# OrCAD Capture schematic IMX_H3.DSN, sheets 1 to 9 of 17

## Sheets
1 PAGE01: title: i.MX28 Home Health Hub; rev: 1.0; company: Freescale Semiconductor; note: SCH-XXXXX PDF: SPF-XXXXX; note: 6501 William Cannon Drive West; note: Austin, TX 78735-8598
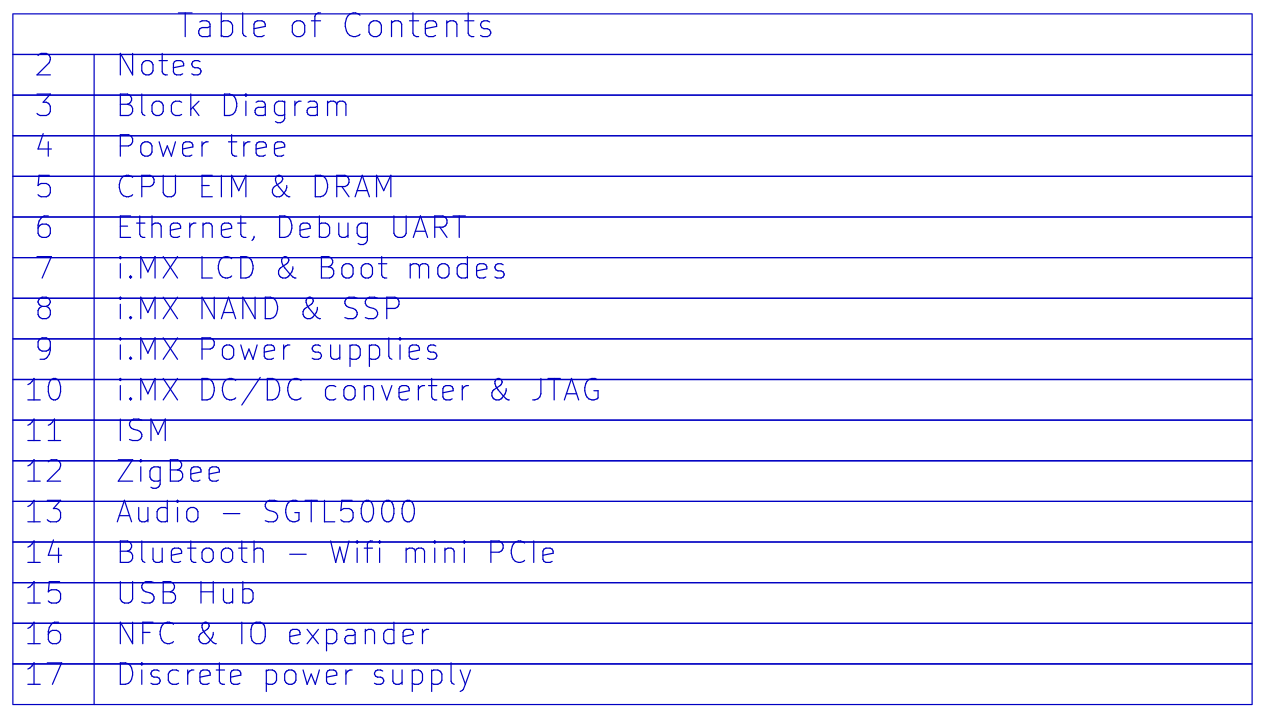
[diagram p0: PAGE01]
2 PAGE02 - Notes & revision table
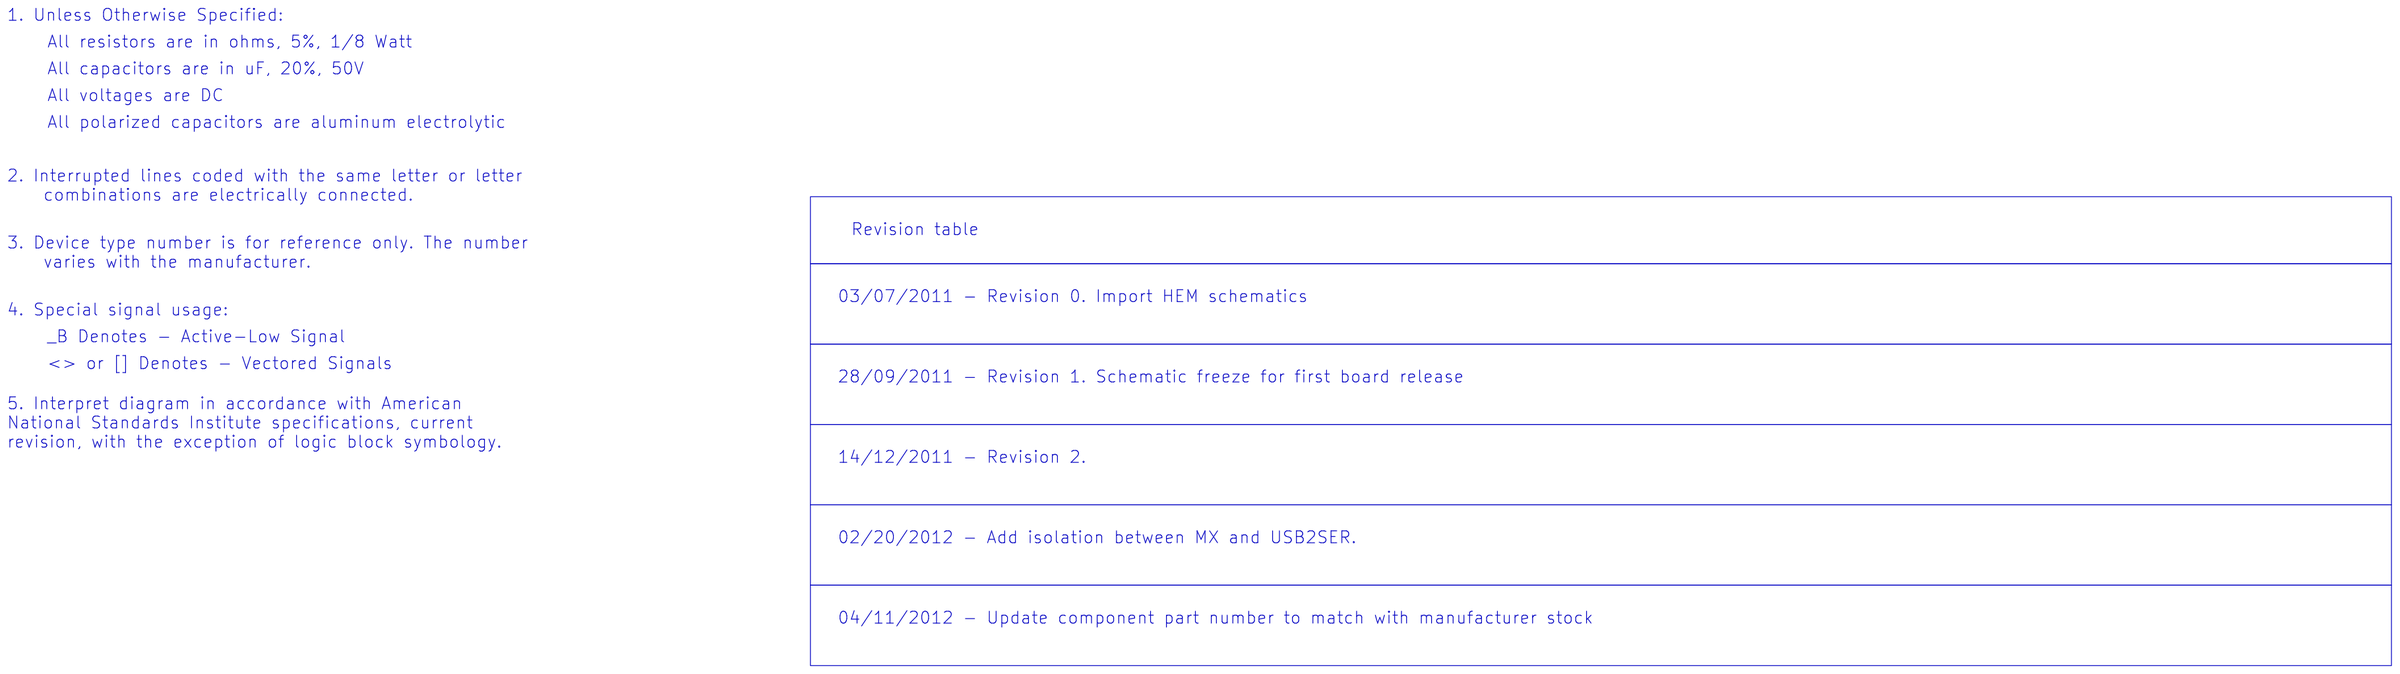
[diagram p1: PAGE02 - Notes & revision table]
3 PAGE03 - Block diagram
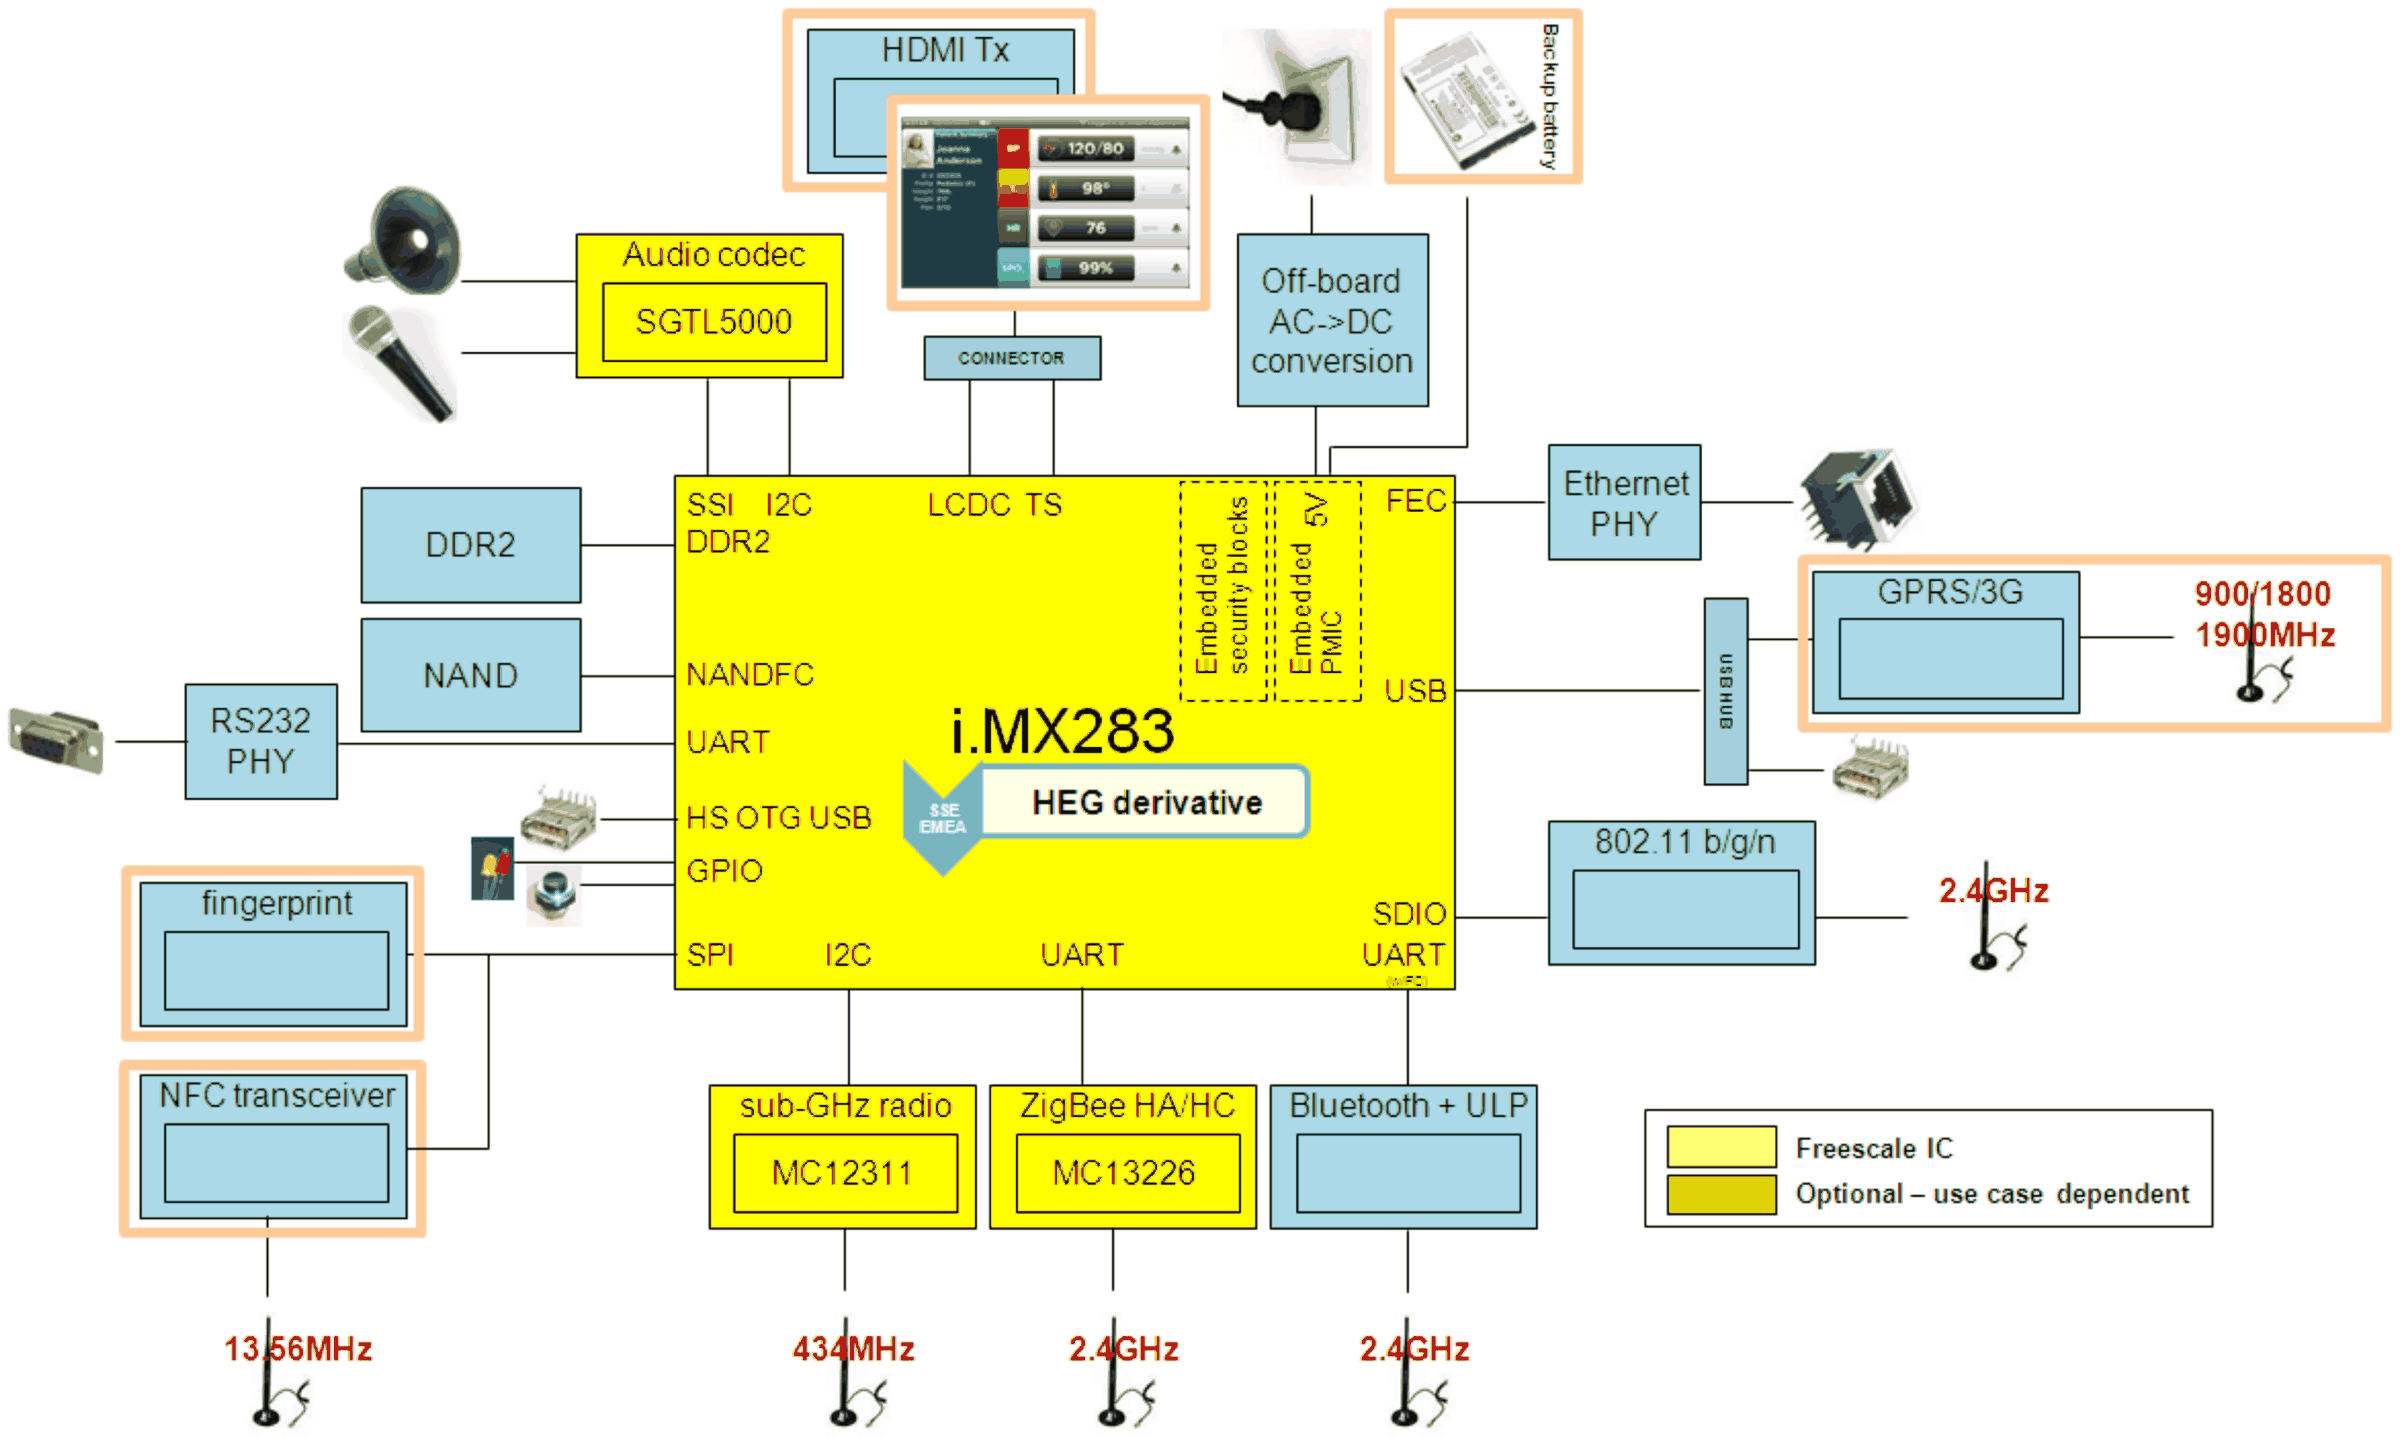
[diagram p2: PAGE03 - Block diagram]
4 PAGE04 - Power Tree
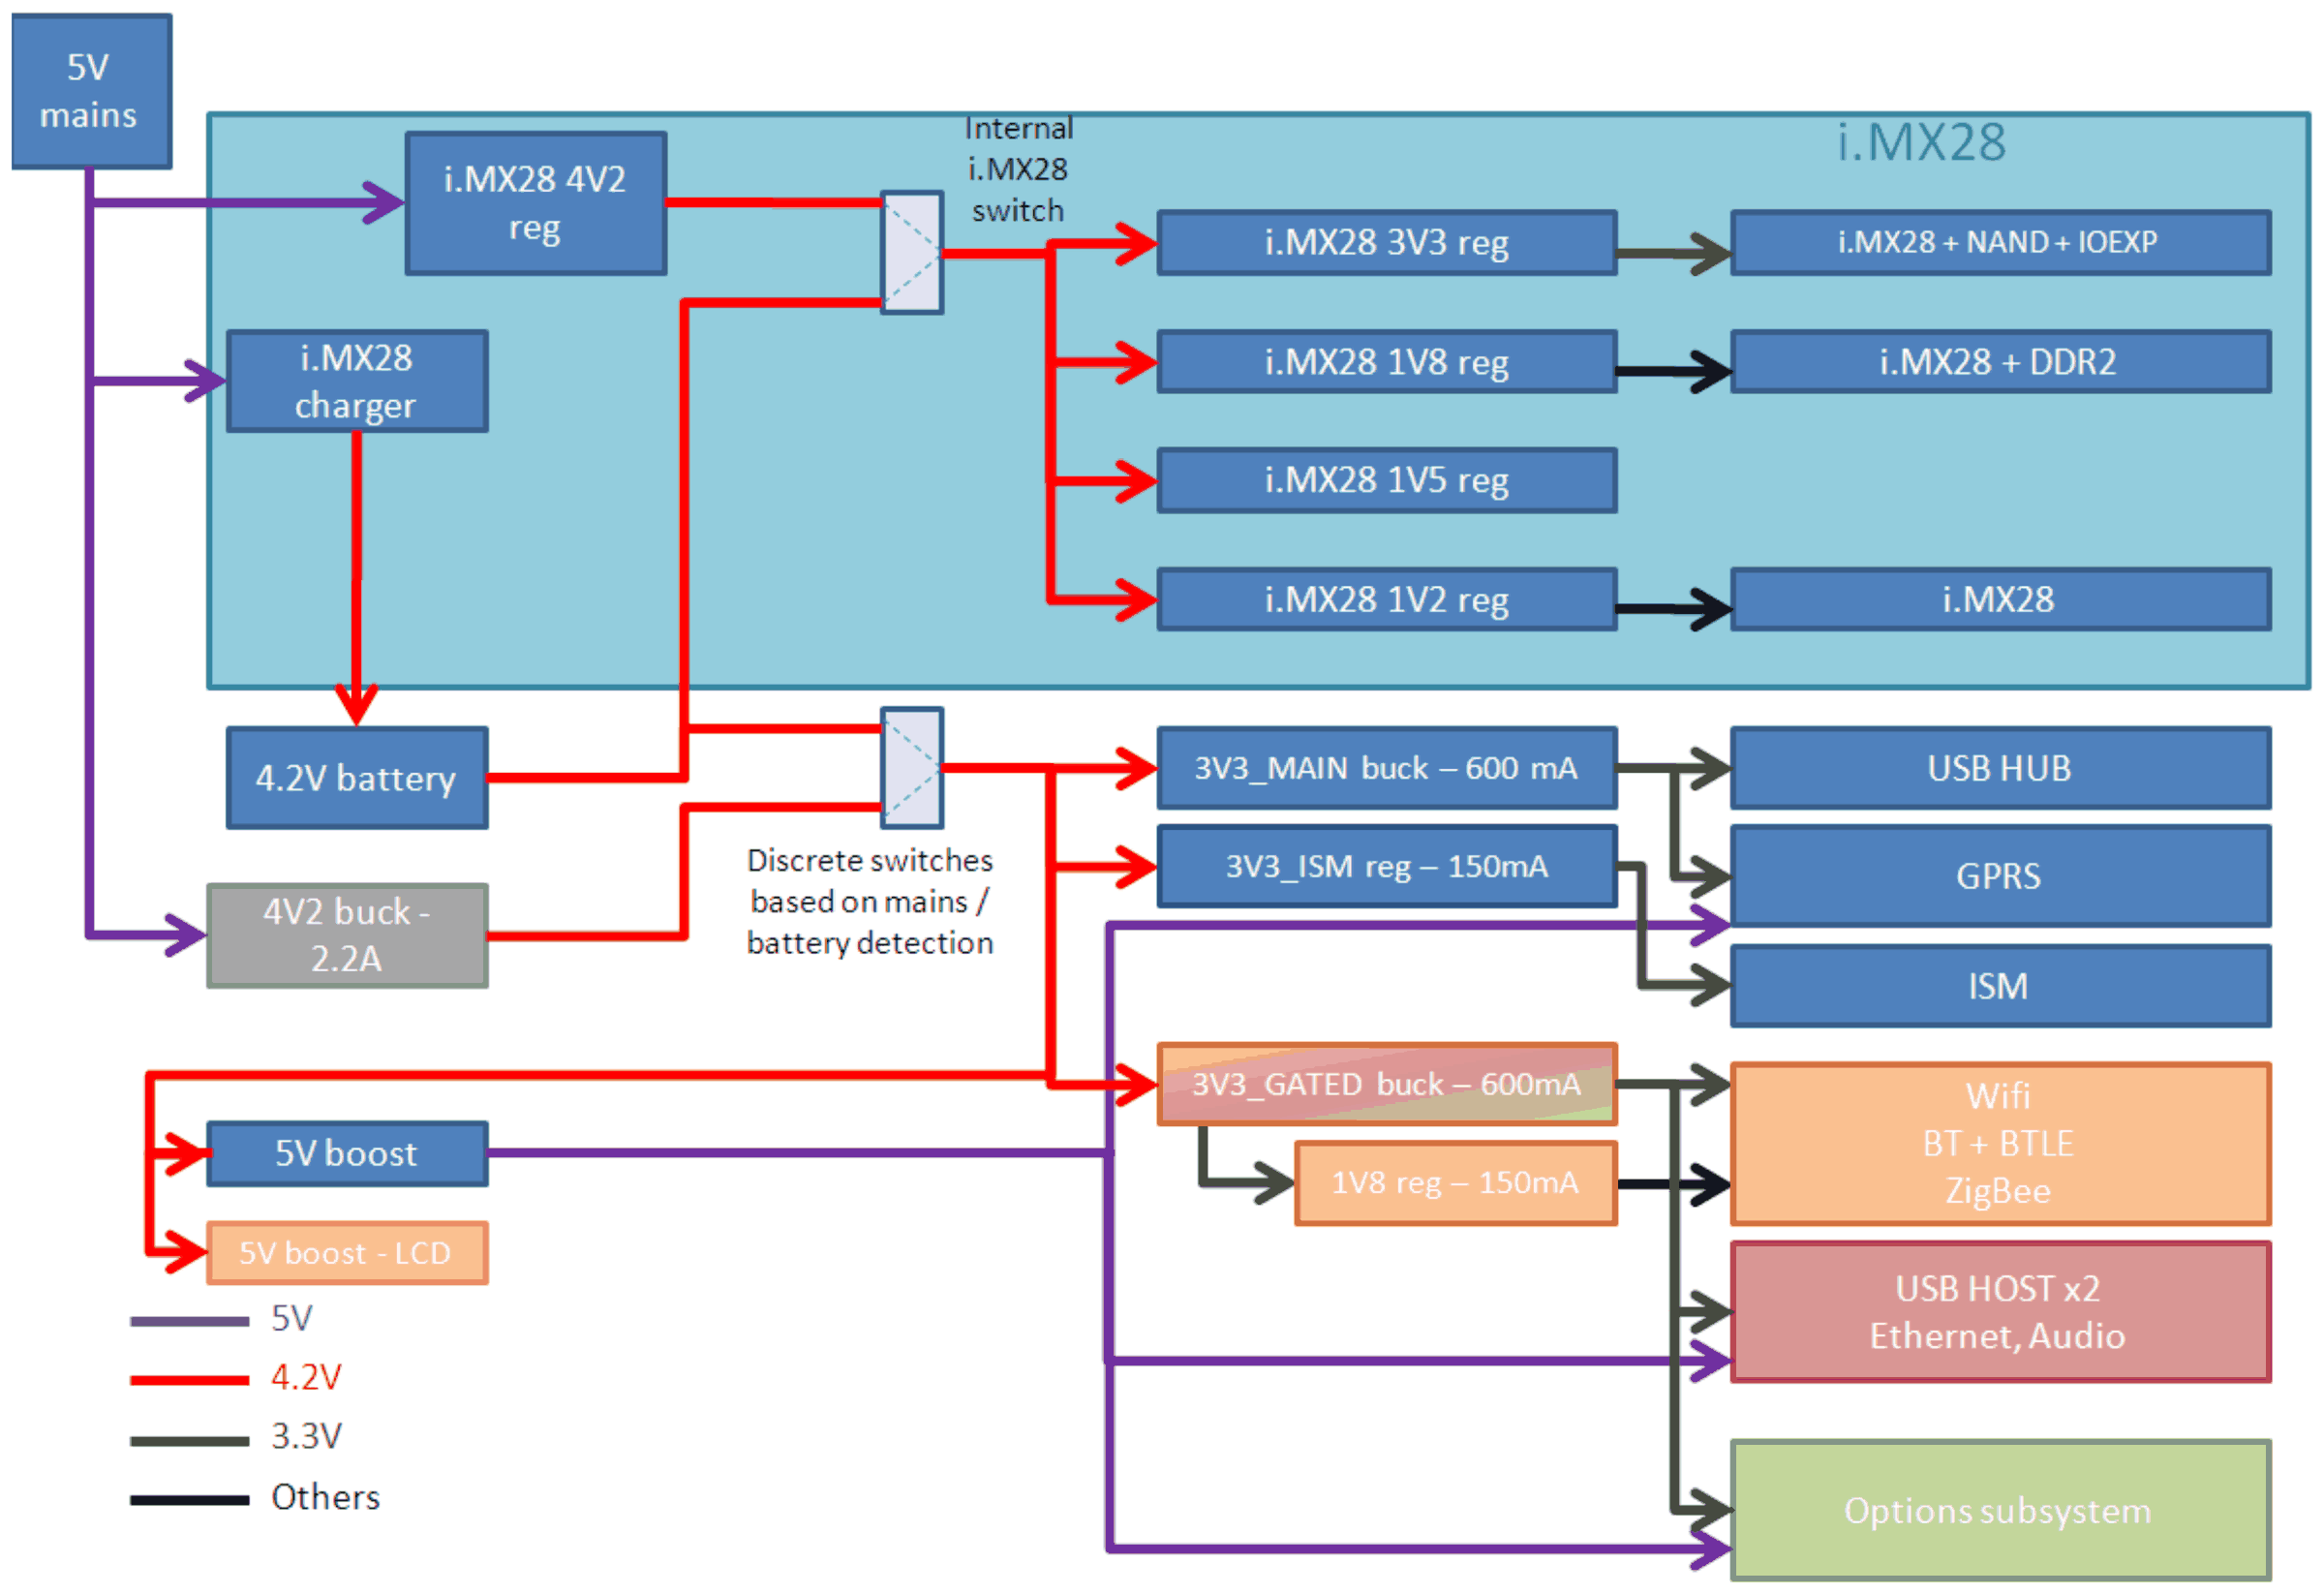
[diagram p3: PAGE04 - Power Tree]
5 PAGE05 - CPU EIM-DRAM: size C
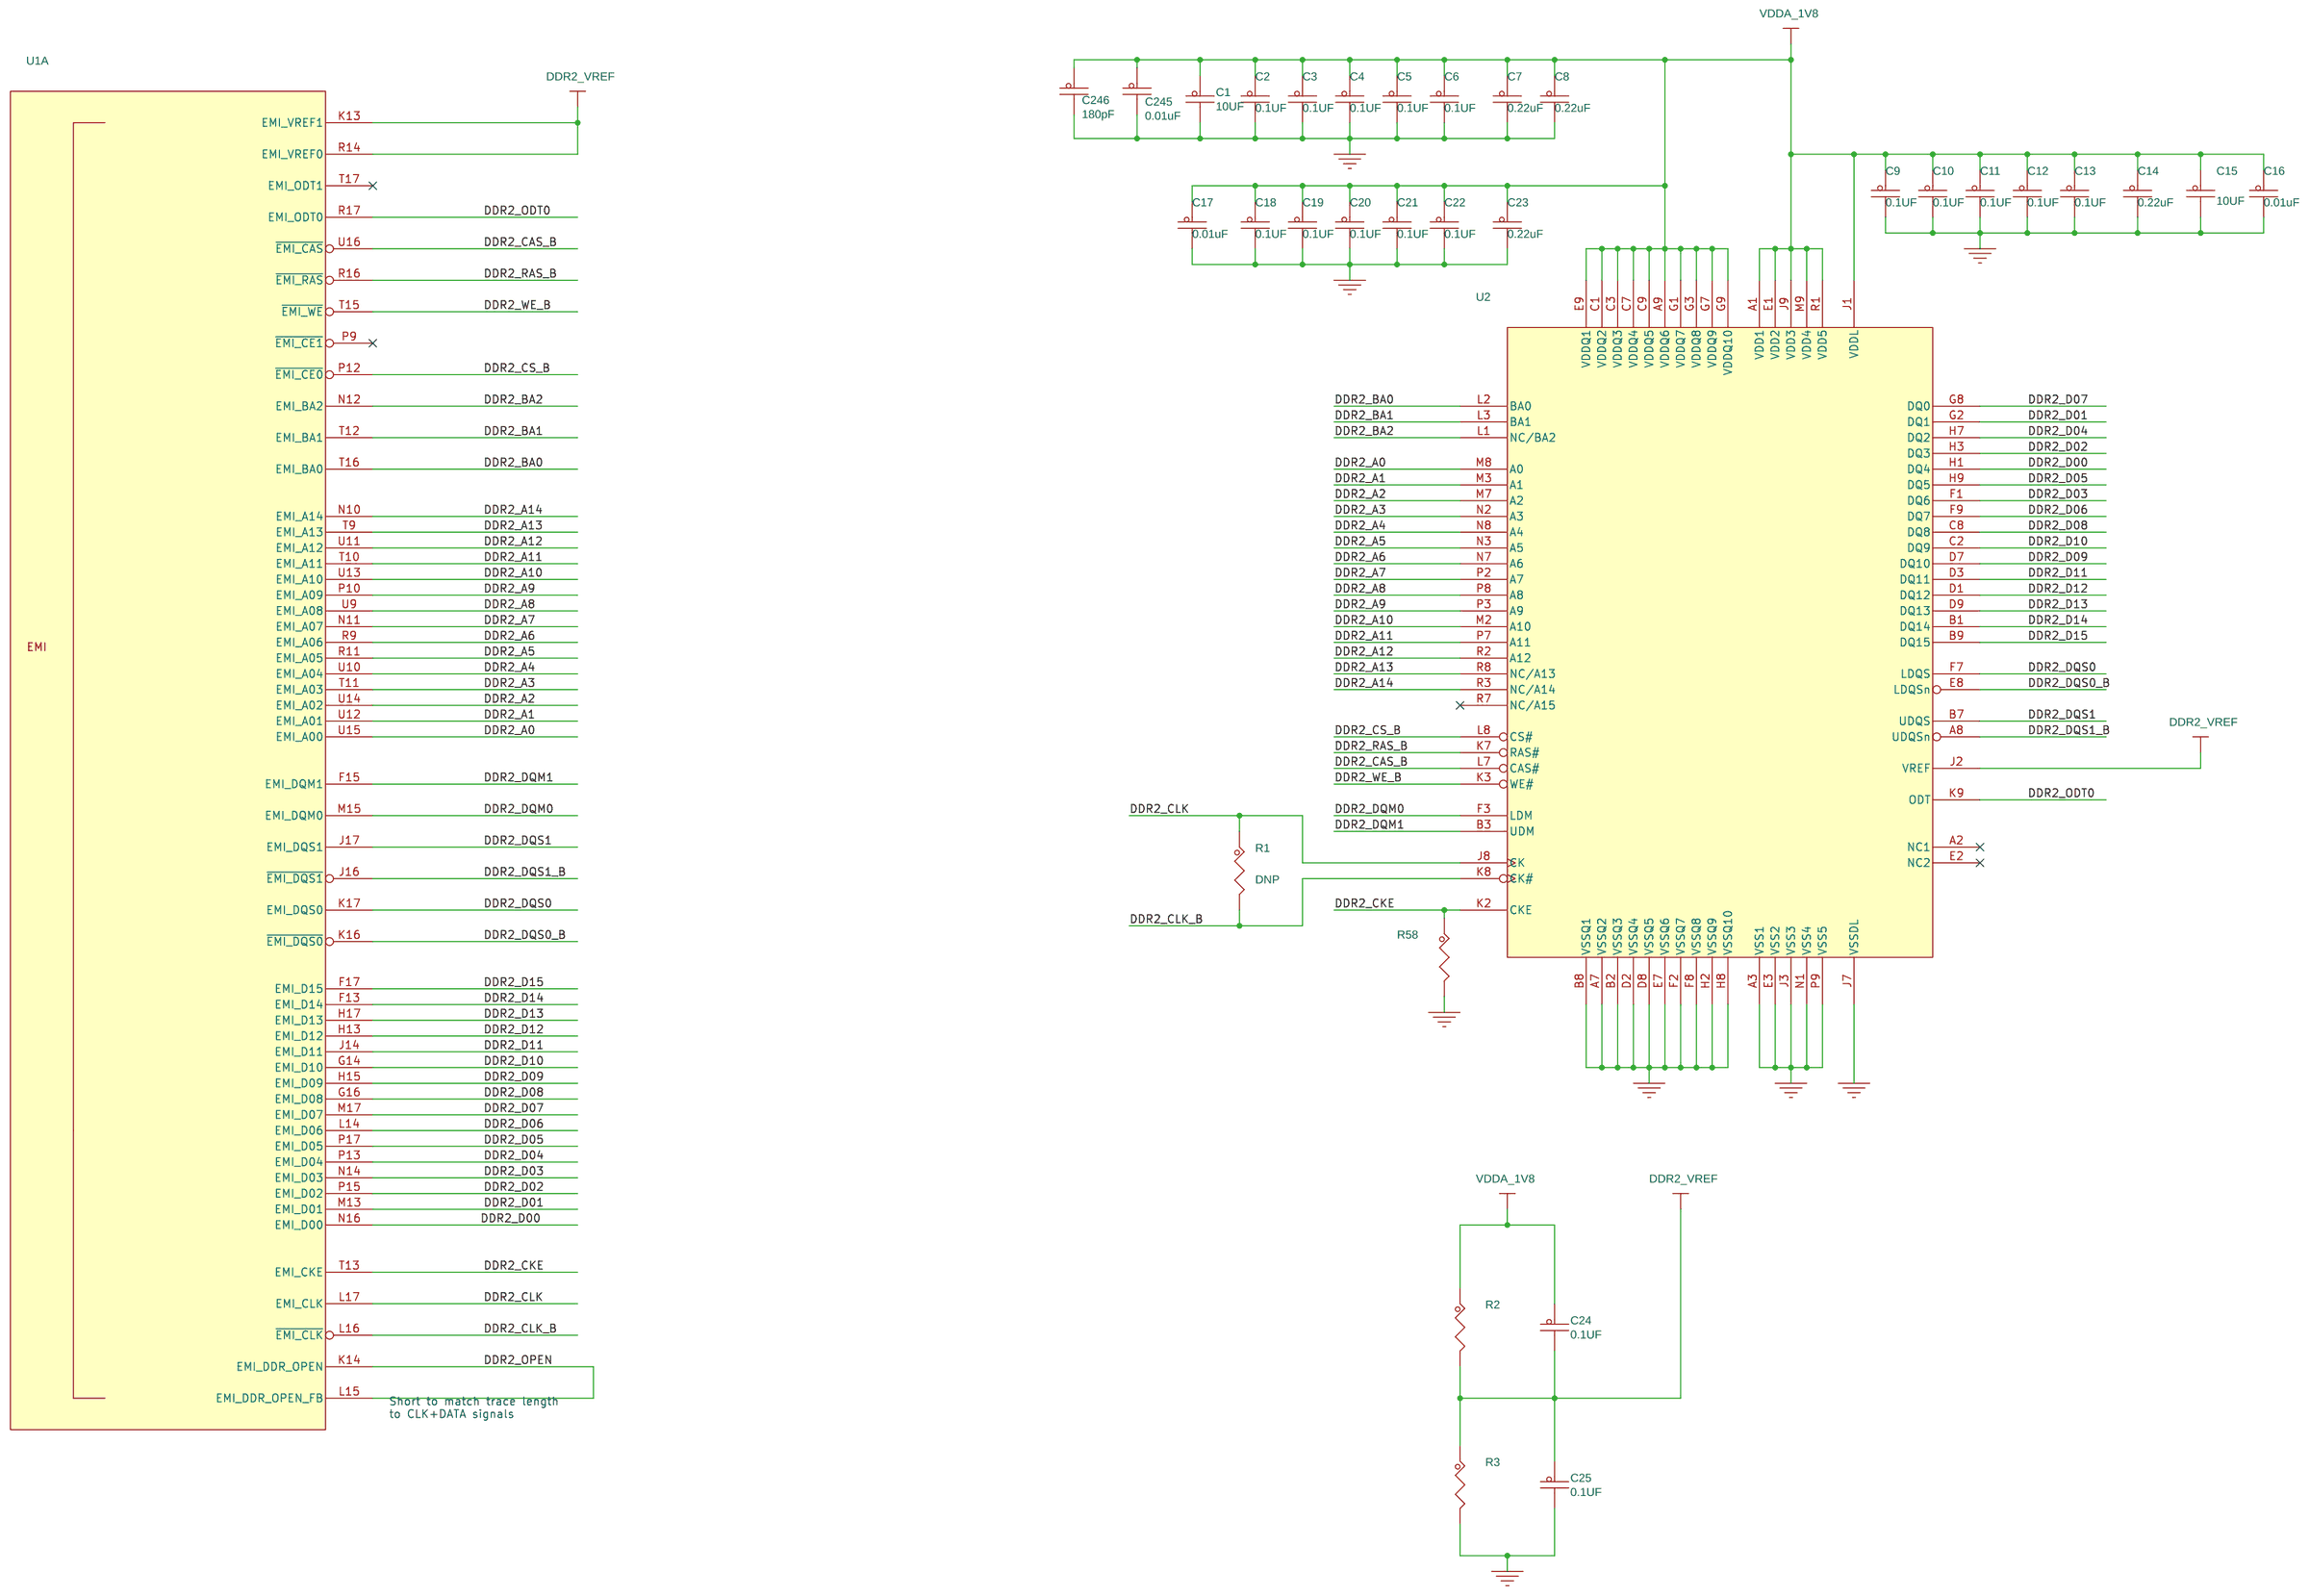
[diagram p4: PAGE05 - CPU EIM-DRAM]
6 PAGE06 - CPU ETH, UART: size C
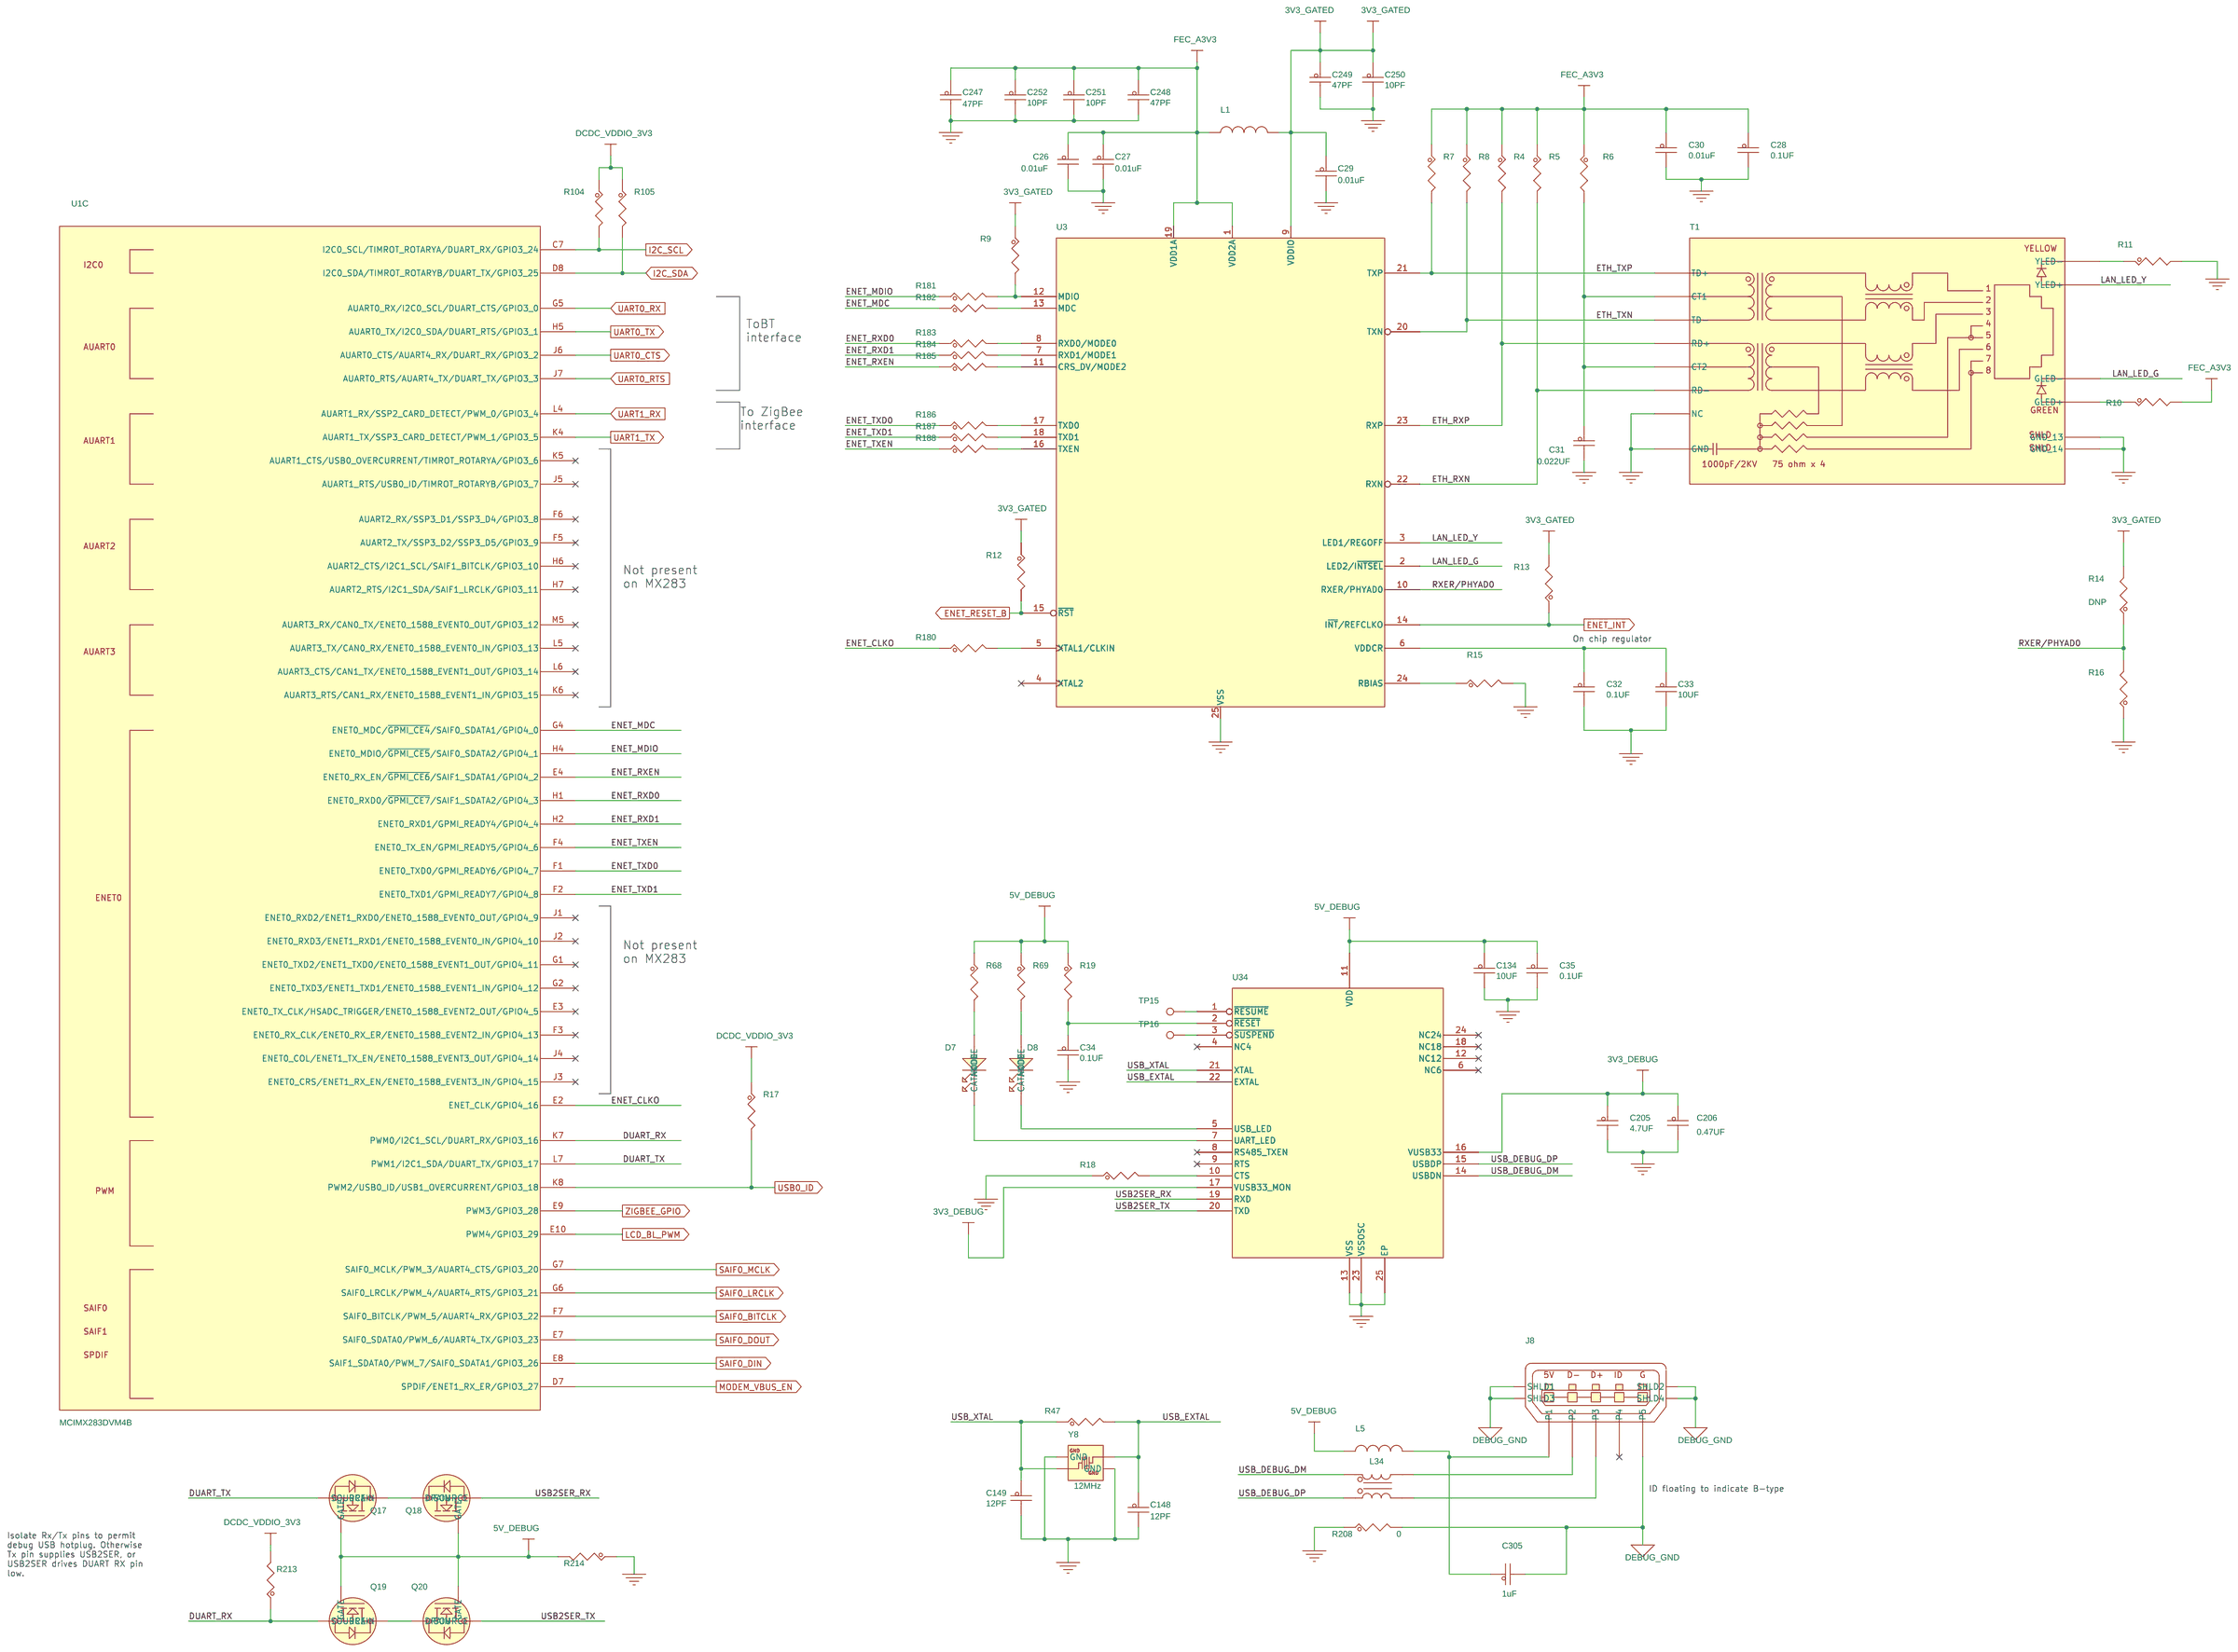
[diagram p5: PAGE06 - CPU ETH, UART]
7 PAGE07 - CPU LCD & LEDs: size C
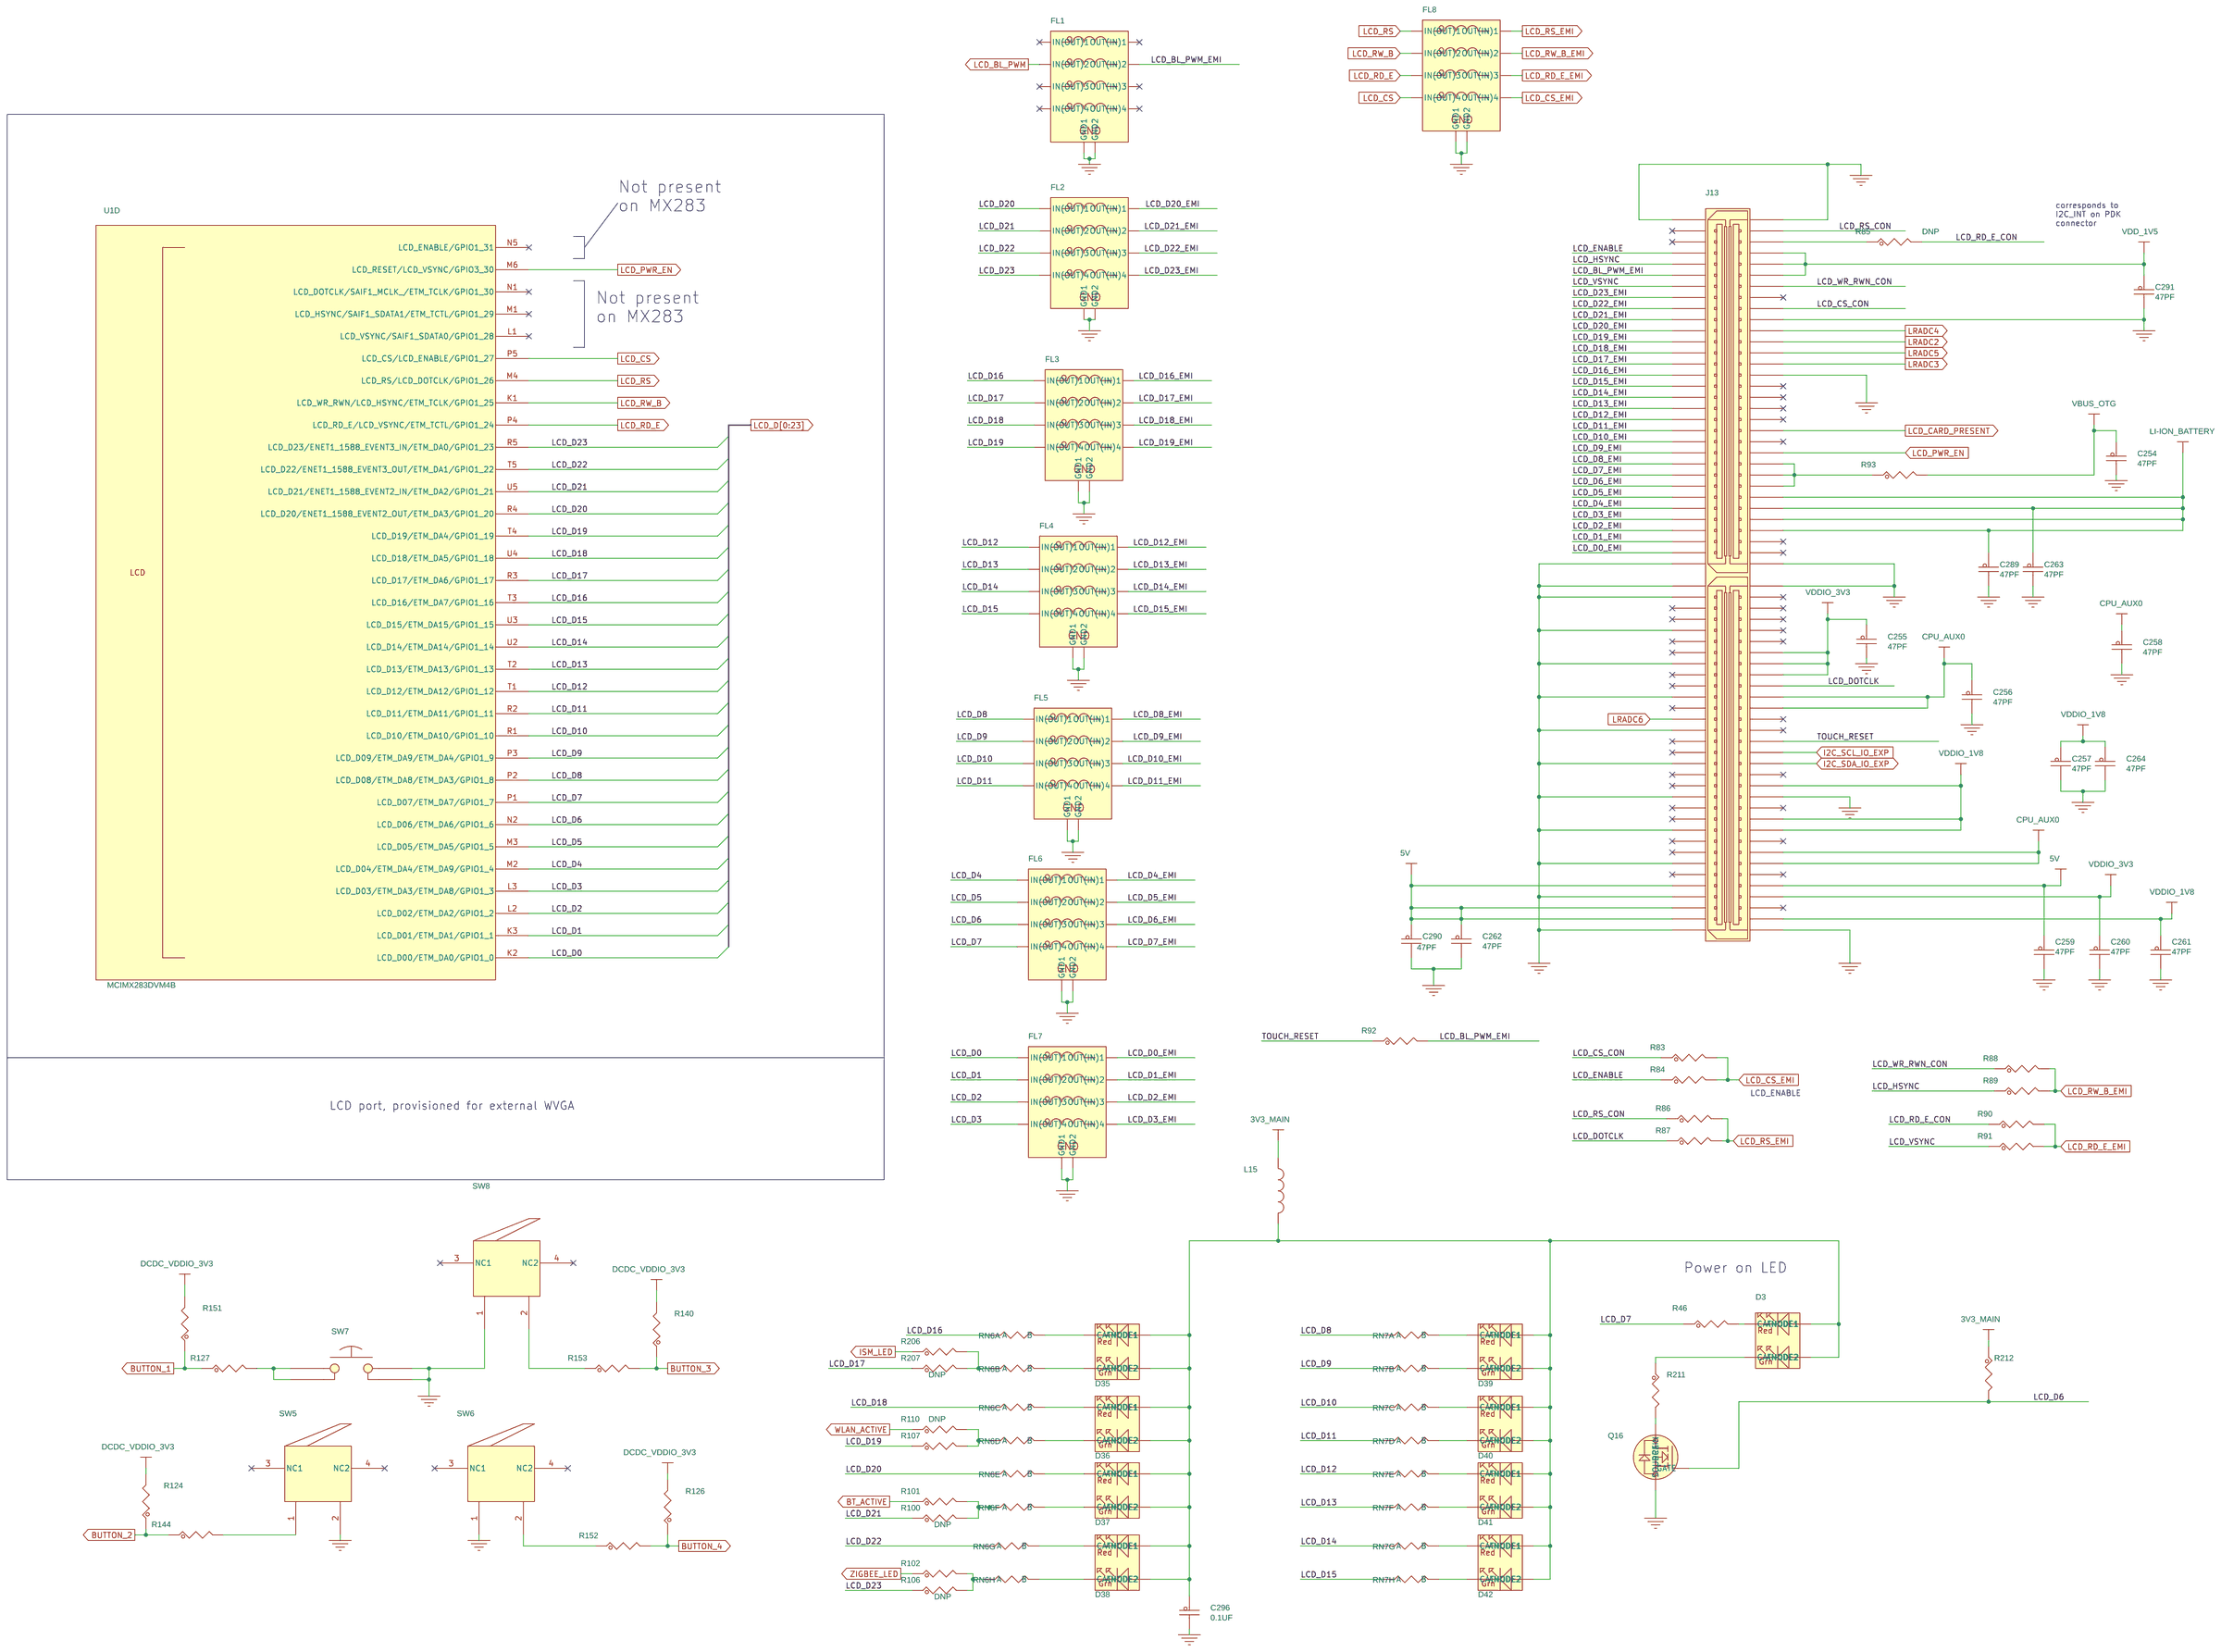
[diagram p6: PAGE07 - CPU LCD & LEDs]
8 PAGE08 - CPU NAND, SSPs: size C
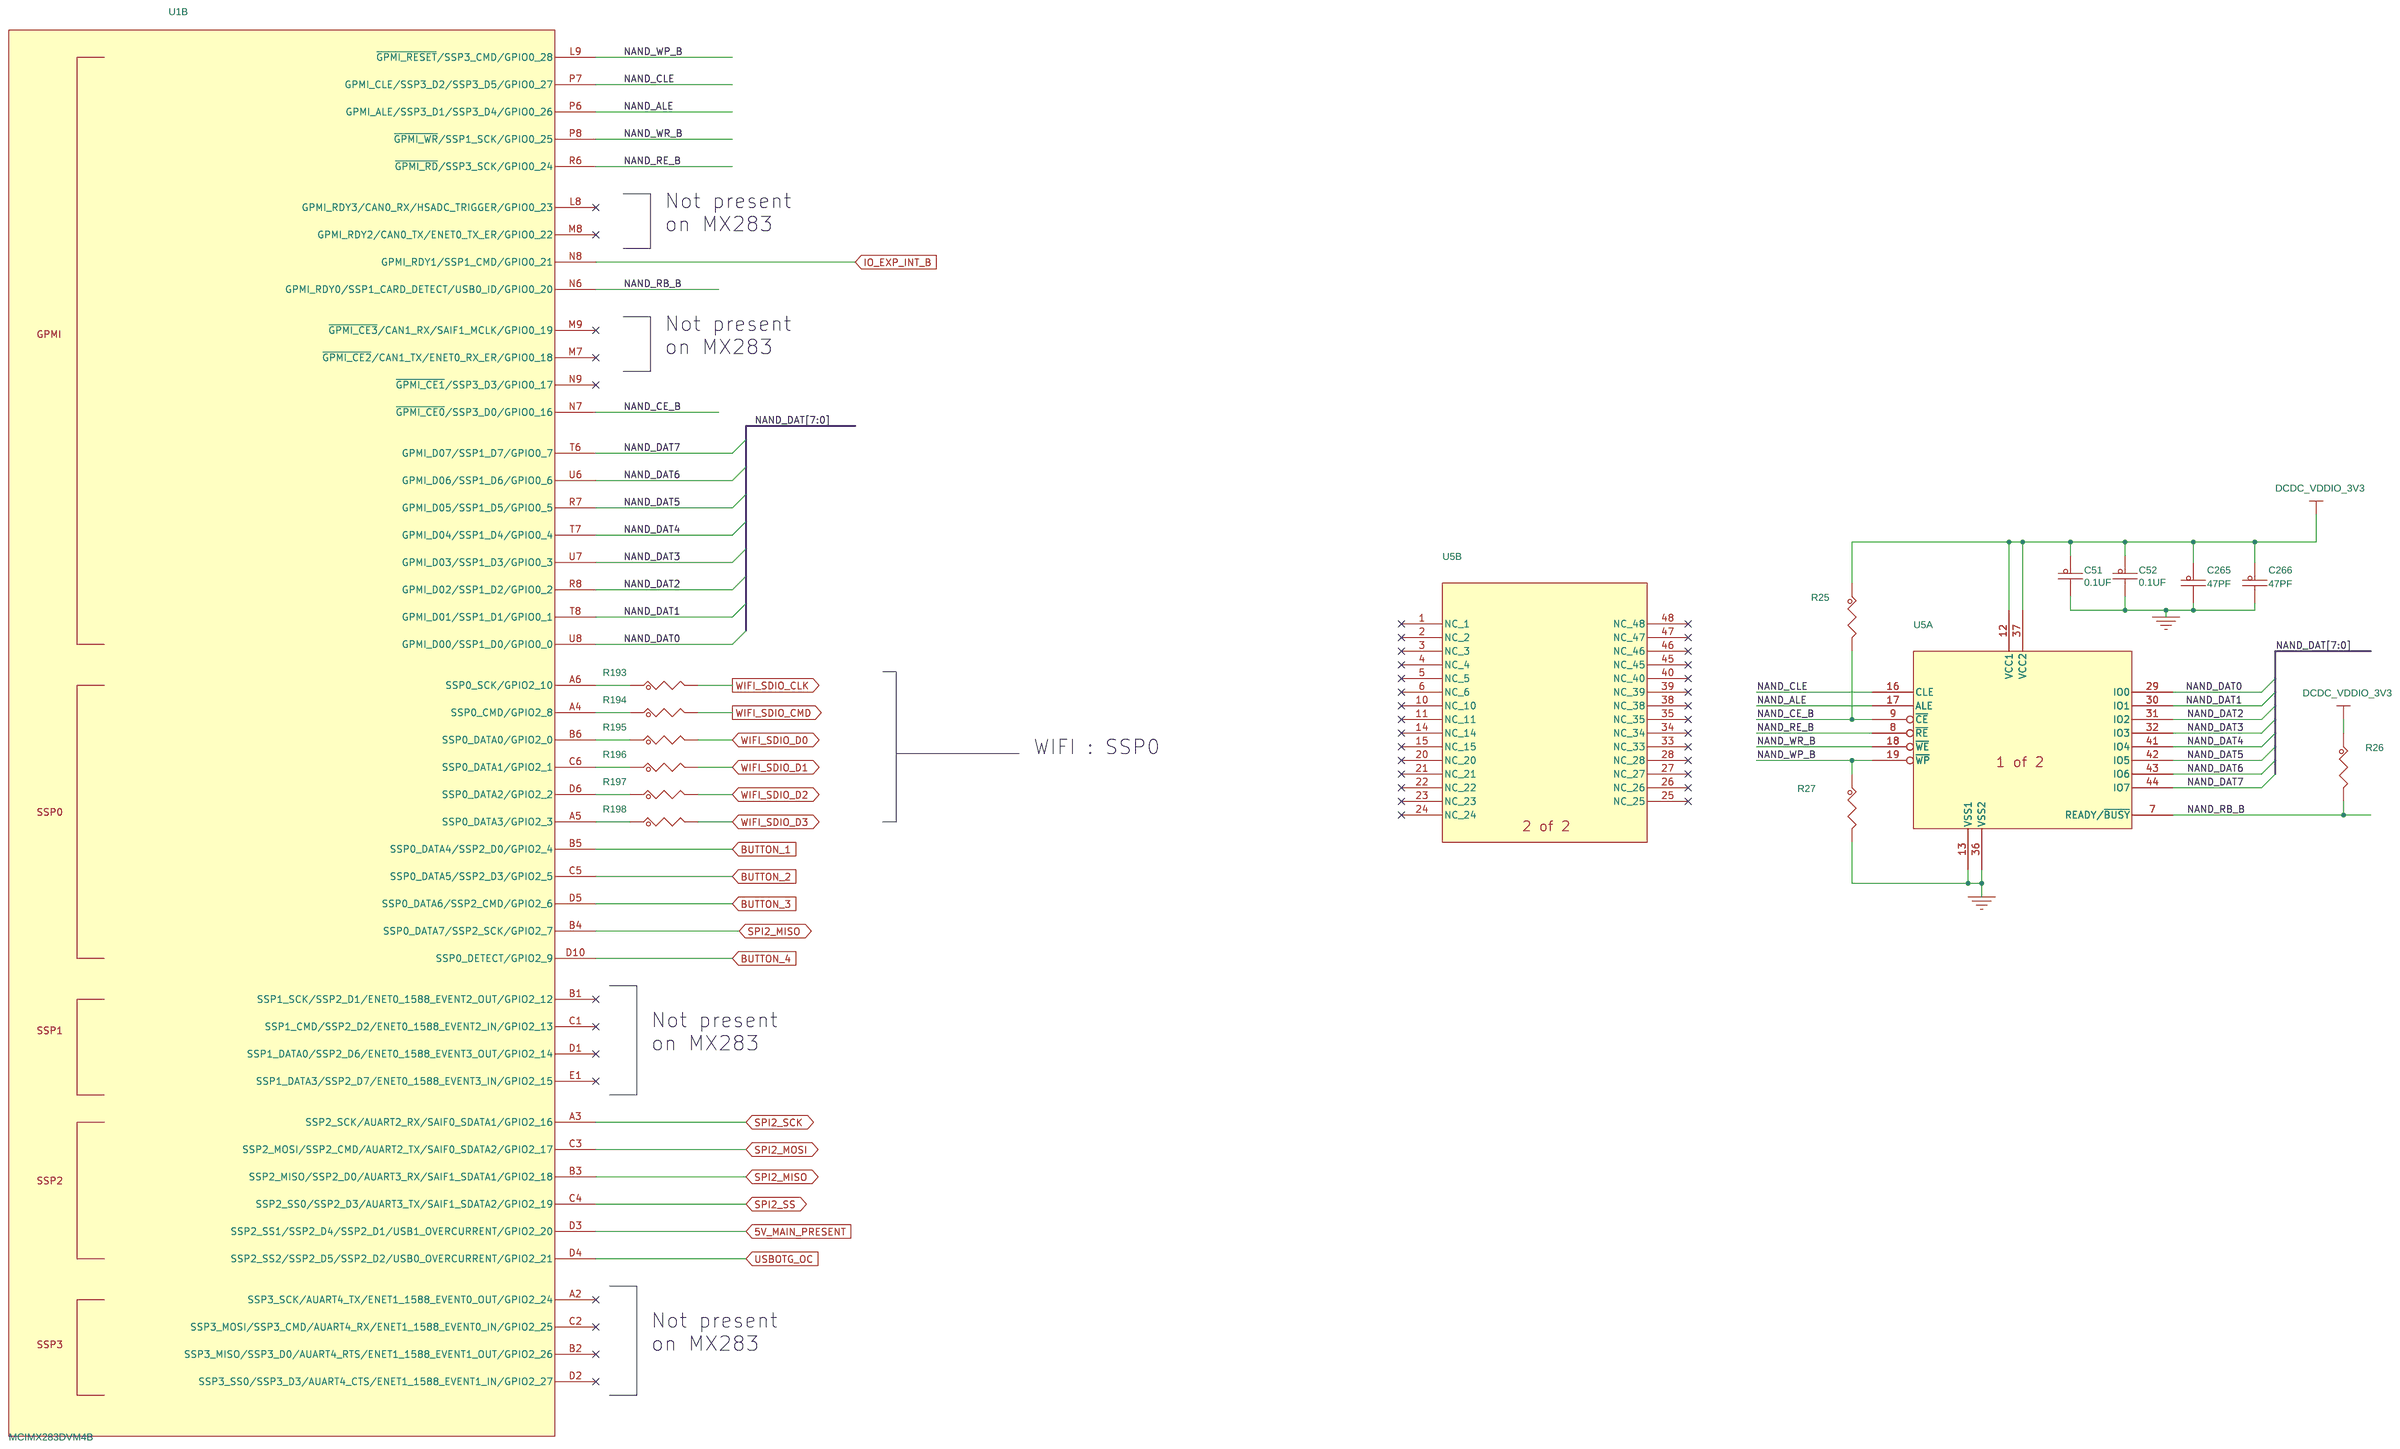
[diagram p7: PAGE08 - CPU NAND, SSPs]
9 PAGE09 - CPU power supply: size C
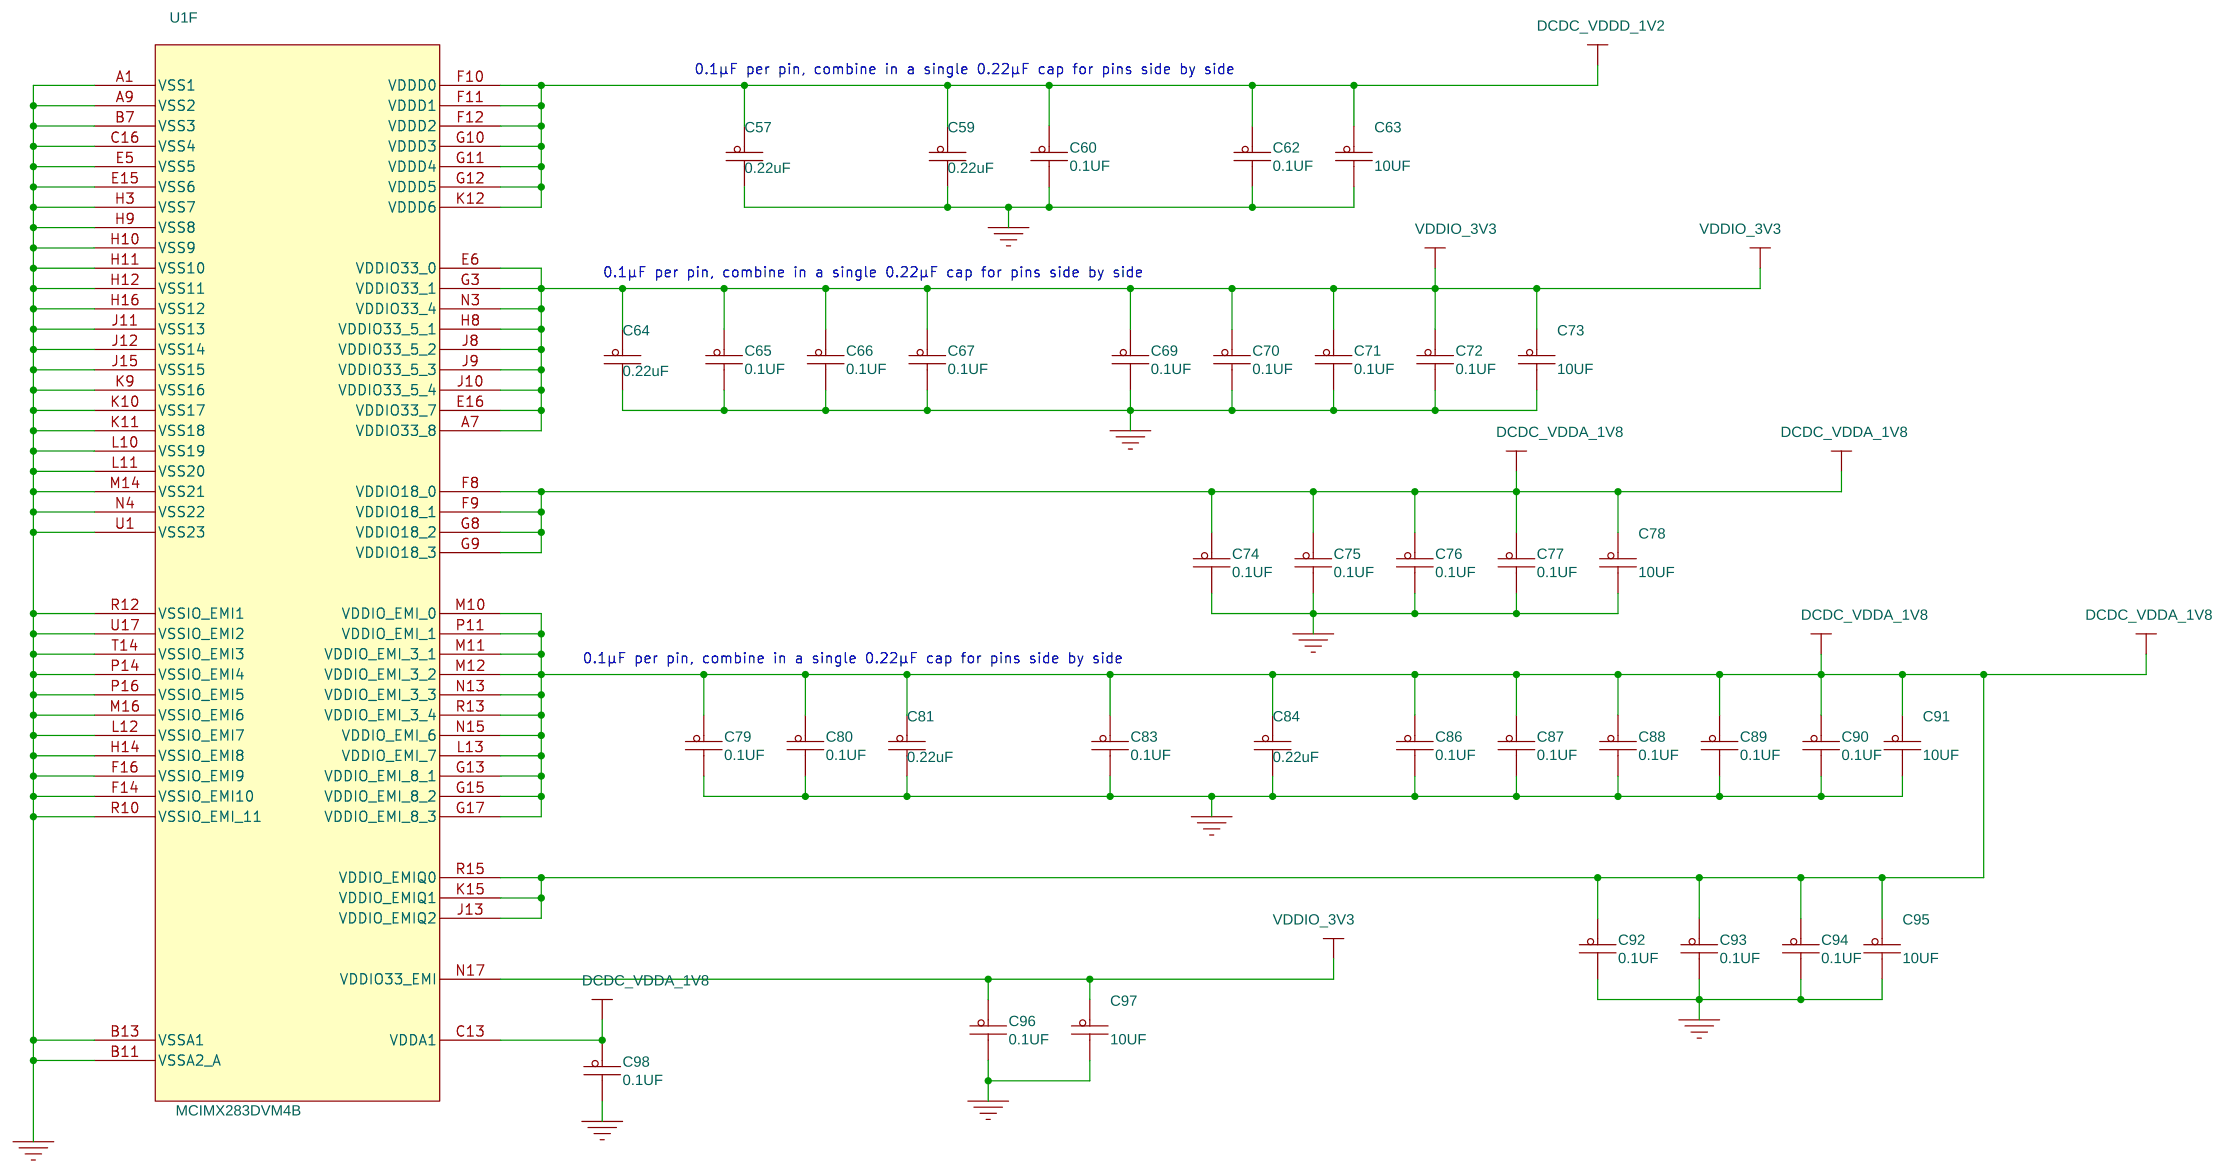
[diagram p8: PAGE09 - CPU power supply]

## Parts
sheet PAGE05 - CPU EIM-DRAM
C1  10UF  [CC0805_OV]
C2  0.1UF  [CC0402_25]
C3  0.1UF  [CC0402_25]
C4  0.1UF  [CC0402_25]
C5  0.1UF  [CC0402_25]
C6  0.1UF  [CC0402_25]
C7  0.22uF  [CC0402_25]
C8  0.22uF  [CC0402_25]
C9  0.1UF  [CC0402_25]
C10  0.1UF  [CC0402_25]
C11  0.1UF  [CC0402_25]
C12  0.1UF  [CC0402_25]
C13  0.1UF  [CC0402_25]
C14  0.22uF  [CC0402_25]
C15  10UF  [CC0805_OV]
C16  0.01uF  [CC0402_25]
C17  0.01uF  [CC0402_25]
C18  0.1UF  [CC0402_25]
C19  0.1UF  [CC0402_25]
C20  0.1UF  [CC0402_25]
C21  0.1UF  [CC0402_25]
C22  0.1UF  [CC0402_25]
C23  0.22uF  [CC0402_25]
C24  0.1UF  [CC0402_25]
C25  0.1UF  [CC0402_25]
C245  0.01uF  [CC0402_25]
C246  180pF  [CC0402_25]
R1  100  [RC0402_25]
R2  1K  [RC0402_25]
R3  1K  [RC0402_25]
R58  10.0K  [RC0402_25]
U2  MT47H64M16HR  [FBGA_84_0p8_10x12p5]
sheet PAGE06 - CPU ETH, UART
C26  0.01uF  [CC0402_25]
C27  0.01uF  [CC0402_25]
C28  0.1UF  [CC0402_25]
C29  0.01uF  [CC0402_25]
C30  0.01uF  [CC0402_25]
C31  0.022UF  [CC0402_25]
C32  0.1UF  [CC0402_25]
C33  10UF  [CC0805_OV]
C34  0.1UF  [CC0402_25]
C35  0.1UF  [CC0402_25]
C134  10UF  [CC0805_OV]
C148  12PF  [CC0402_25]
C149  12PF  [CC0402_25]
C205  4.7UF  [CC0603_OV]
C206  0.47UF  [CC0402_25]
C247  47PF  [CC0402_25]
C248  47PF  [CC0402_25]
C249  47PF  [CC0402_25]
C250  10PF  [CC0402_25]
C251  10PF  [CC0402_25]
C252  10PF  [CC0402_25]
C305  1uF  [CC0603_OV]
D7  LED_GREEN  [LED_0603]
D8  LED_GREEN  [LED_0603]
J8  MICRO USB AB 5  [con5_microusb]
L1  470OHM  [IND_0603]
L5  470OHM  [IND_0603]
L34  90 OHM@100MHZ  [IND_0805_4P]
Q17  NTS4001NT1G  [sc70_3]
Q18  NTS4001NT1G  [sc70_3]
Q19  NTS4001NT1G  [sc70_3]
Q20  NTS4001NT1G  [sc70_3]
R4  49.9  [RC0402_25]
R5  49.9  [RC0402_25]
R6  0  [RC0402_25]
R7  49.9  [RC0402_25]
R8  49.9  [RC0402_25]
R9  4.7K  [RC0402_25]
R10  270  [RC0402_25]
R11  270  [RC0402_25]
R12  10.0K  [RC0402_25]
R13  10.0K  [RC0402_25]
R14  10.0K  [RC0402_25]
R15  12.1K  [RC0402_25]
R16  10.0K  [RC0402_25]
R17  10.0K  [RC0402_25]
R18  10.0K  [RC0402_25]
R19  10.0K  [RC0402_25]
R47  1.0M  [RC0402_25]
R68  453  [RC0402_25]
R69  453  [RC0402_25]
R104  4.7K  [RC0402_25]
R105  4.7K  [RC0402_25]
R180  10  [RC0402_25]
R181  10  [RC0402_25]
R182  10  [RC0402_25]
R183  10  [RC0402_25]
R184  10  [RC0402_25]
R185  10  [RC0402_25]
R186  10  [RC0402_25]
R187  10  [RC0402_25]
R188  10  [RC0402_25]
R208  0  [RC0603_OV]
R213  10.0K  [RC0402_25]
R214  1.0M  [RC0402_25]
T1  RJ45-8  [HFJ11-2450E-L12RL]
TP15  35 MIL  [TESTPOINT_35MIL]
TP16  35 MIL  [TESTPOINT_35MIL]
U3  LAN8720A  [qfn24_4X4mm_slug]
U34  USB2SERA10CFK  [qfn24_0p65_5x5]
Y8  12MHz  [xtlosc4_3p2x2p5mm_sm]
sheet PAGE07 - CPU LCD & LEDs
C254  47PF  [CC0402_25]
C255  47PF  [CC0402_25]
C256  47PF  [CC0402_25]
C257  47PF  [CC0402_25]
C258  47PF  [CC0402_25]
C259  47PF  [CC0402_25]
C260  47PF  [CC0402_25]
C261  47PF  [CC0402_25]
C262  47PF  [CC0402_25]
C263  47PF  [CC0402_25]
C264  47PF  [CC0402_25]
C289  47PF  [CC0402_25]
C290  47PF  [CC0402_25]
C291  47PF  [CC0402_25]
C296  0.1UF  [CC0402_25]
D3  LED_RED-GRN  [led_dual_0605_sm]
D35  LED_RED-GRN  [led_dual_0605_sm]
D36  LED_RED-GRN  [led_dual_0605_sm]
D37  LED_RED-GRN  [led_dual_0605_sm]
D38  LED_RED-GRN  [led_dual_0605_sm]
D39  LED_RED-GRN  [led_dual_0605_sm]
D40  LED_RED-GRN  [led_dual_0605_sm]
D41  LED_RED-GRN  [led_dual_0605_sm]
D42  LED_RED-GRN  [led_dual_0605_sm]
FL1  NFA18SL307  [filter_nfa18sd]
FL2  NFA18SL307  [filter_nfa18sd]
FL3  NFA18SL307  [filter_nfa18sd]
FL4  NFA18SL307  [filter_nfa18sd]
FL5  NFA18SL307  [filter_nfa18sd]
FL6  NFA18SL307  [filter_nfa18sd]
FL7  NFA18SL307  [filter_nfa18sd]
FL8  NFA18SL307  [filter_nfa18sd]
J13  QSH-060-01-L-D-A  [CON_120S_QSH_SM_05PITCH]
L15  470OHM  [IND_0603]
Q16  NTS4001NT1G  [sc70_3]
R46  453  [RC0402_25]
R83  0  [RC0402_25]
R84  0  [RC0402_25]
R85  0  [RC0402_25]
R86  0  [RC0402_25]
R87  0  [RC0402_25]
R88  0  [RC0402_25]
R89  0  [RC0402_25]
R90  0  [RC0402_25]
R91  0  [RC0402_25]
R92  0  [RC0402_25]
R93  0  [RC0603_OV]
R100  0  [RC0402_25]
R101  0  [RC0402_25]
R102  0  [RC0402_25]
R106  0  [RC0402_25]
R107  0  [RC0402_25]
R110  0  [RC0402_25]
R124  47K  [RC0402_25]
R126  47K  [RC0402_25]
R127  4.7K  [RC0402_25]
R140  47K  [RC0402_25]
R144  4.7K  [RC0402_25]
R151  47K  [RC0402_25]
R152  4.7K  [RC0402_25]
R153  4.7K  [RC0402_25]
R206  0  [RC0402_25]
R207  0  [RC0402_25]
R211  453  [RC0402_25]
R212  10.0K  [RC0402_25]
RN6  470  [RCA8_16]  (sections A,B,C,D,E,F,G,H)
RN7  470  [RCA8_16]  (sections A,B,C,D,E,F,G,H)
SW5  ATCA Handle Switch  [SW2_SPST_PB_RA]
SW6  ATCA Handle Switch  [SW2_SPST_PB_RA]
SW7  EVQPUA02K  [sw_spst_pb_4p8x3p5_sm]
SW8  ATCA Handle Switch  [SW2_SPST_PB_RA]
U1  MCIMX283DVM4B  [bga289_0p8_14x14]  (sections A,B,C,D,E,F)
sheet PAGE08 - CPU NAND, SSPs
C51  0.1UF  [CC0402_25]
C52  0.1UF  [CC0402_25]
C265  47PF  [CC0402_25]
C266  47PF  [CC0402_25]
R25  10.0K  [RC0402_25]
R26  10.0K  [RC0402_25]
R27  47K  [RC0402_25]
R193  10  [RC0402_25]
R194  10  [RC0402_25]
R195  10  [RC0402_25]
R196  10  [RC0402_25]
R197  10  [RC0402_25]
R198  10  [RC0402_25]
U5  MT29F4G08ABADAWP  [tsop48]  (sections A,B)
sheet PAGE09 - CPU power supply
C57  0.22uF  [CC0402_25]
C59  0.22uF  [CC0402_25]
C60  0.1UF  [CC0402_25]
C62  0.1UF  [CC0402_25]
C63  10UF  [CC0805_OV]
C64  0.22uF  [CC0402_25]
C65  0.1UF  [CC0402_25]
C66  0.1UF  [CC0402_25]
C67  0.1UF  [CC0402_25]
C69  0.1UF  [CC0402_25]
C70  0.1UF  [CC0402_25]
C71  0.1UF  [CC0402_25]
C72  0.1UF  [CC0402_25]
C73  10UF  [CC0805_OV]
C74  0.1UF  [CC0402_25]
C75  0.1UF  [CC0402_25]
C76  0.1UF  [CC0402_25]
C77  0.1UF  [CC0402_25]
C78  10UF  [CC0805_OV]
C79  0.1UF  [CC0402_25]
C80  0.1UF  [CC0402_25]
C81  0.22uF  [CC0402_25]
C83  0.1UF  [CC0402_25]
C84  0.22uF  [CC0402_25]
C86  0.1UF  [CC0402_25]
C87  0.1UF  [CC0402_25]
C88  0.1UF  [CC0402_25]
C89  0.1UF  [CC0402_25]
C90  0.1UF  [CC0402_25]
C91  10UF  [CC0805_OV]
C92  0.1UF  [CC0402_25]
C93  0.1UF  [CC0402_25]
C94  0.1UF  [CC0402_25]
C95  10UF  [CC0805_OV]
C96  0.1UF  [CC0402_25]
C97  10UF  [CC0805_OV]
C98  0.1UF  [CC0402_25]

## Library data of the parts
C1 C15 C33 C63 C78 C91 C95 C97 C134 = CAP_NP: CAP CER 10UF 10V 10% X5R 0805; CAD_APPROVED: Yes; FPLIST: CC0805_OV,CC0805,0805_CC; HEIGHT: 1.45 MM; MFG_NAME01: SAMSUNG; MFG_PN01: CL21A106KPFNNNE; ROHS: Yes; Tolerance: 10%
C2-C6 C9-C13 C18-C22 C24 C25 C28 C32 C34 C35 C51 C52 C60 C62 C65-C67 C69-C72 C74-C77 C79 C80 C83 C86-C90 C92-C94 C96 C98 C296 = CAP_NP: CAP CER 0.1UF 10V 10% X5R 0402; AGILE_PN: 150-75634; CAD_APPROVED: Yes; FPLIST: CC0402_25,CC0402_HD,0402_CC; HEIGHT: 0.60MM; MFG_NAME01: KEMET; MFG_PN01: C0402C104K8PAC; ROHS: Yes; Tolerance: 10%
C7 C8 C14 C23 C57 C59 C64 C81 C84 = CAP_NP: CAP CER 0.22UF 6.3V 20% X5R 0402; AGILE_PN: 150-76271; CAD_APPROVED: Yes; FPLIST: CC0402_25,CC0402_HD,0402_CC; HEIGHT: 0.55MM; MFG_NAME01: KEMET; MFG_PN01: C0402C224M9PAC; ROHS: Yes; Tolerance: 20%
C16 C17 C26 C27 C29 C30 C245 = CAP_NP: CAP CER 0.01UF 25V 10% X7R 0402; CAD_APPROVED: Yes; FPLIST: CC0402_25,CC0402_HD,0402_CC; HEIGHT: 0.55MM; MFG_NAME01: AVX; MFG_PN01: 04023C103KAT2A; ROHS: Yes; Tolerance: 10%
C246 = CAP_NP: CAP CER 180PF 50V 5% C0G 0402; CAD_APPROVED: Yes; FPLIST: CC0402_25,CC0402_HD,0402_CC; HEIGHT: 0.6mm; MFG_NAME01: Murata; MFG_PN01: GRM1555C1H181JA01D; ROHS: Yes; Tolerance: 5%
R1 = RES: RES MF 100 OHM 1/16W 1% 0402; AGILE_PN: 470-30454; ASSY_OPT: DNP; CAD_APPROVED: Yes; FPLIST: RC0402_25,RC0402_HD,0402_CC; MFG_NAME01: THYE MING TECH CO LTD; MFG_PN01: CR-02FL6--100R; ROHS: Yes; Tolerance: 1%
R2 R3 = RES: RES MF 1.0K 1/16W 5% 0402; AGILE_PN: 470-75555; CAD_APPROVED: Yes; FPLIST: RC0402_25,RC0402_HD,RC0402_X2,0402_CC; MFG_NAME01: VISHAY INTERTECHNOLOGY; MFG_PN01: CRCW04021K00JNED; ROHS: Yes; Tolerance: 5%
R12 R13 R16-R19 R25 R26 R58 R212 R213 = RES: RES MF 10.0K 1/16W 1% 0402; AGILE_PN: 470-75416; CAD_APPROVED: Yes; FPLIST: RC0402_25,RC0402_HD,0402_CC; MFG_NAME01: KOA SPEER; MFG_PN01: RK73H1ETTP1002F; ROHS: Yes; Tolerance: 1%
U2 = MT47H32M16BN-37E: IC MEM DDR2 SDRAM 64MBX16 3.75NS 1.8V FBGA84; AGILE_PN: 334-76178; CAD_APPROVED: Yes; HEIGHT: 1.2MM; MFG_NAME01: MICRON; MFG_PN01: MT47H64M16HR-25E:H; ROHS: Yes
C31 = CAP_NP: CAP CER 0.022UF 50V 10% X7R 0402; CAD_APPROVED: Yes; FPLIST: CC0402_25,CC0402_HD,0402_CC; HEIGHT: 0.55MM; MFG_NAME01: MURATA; MFG_PN01: GRM155R71H223KA12; ROHS: Yes; Tolerance: 10%
C148 C149 = CAP_NP: CAP CER 12PF 50V 5% C0G 0402; AGILE_PN: 150-75680; CAD_APPROVED: Yes; FPLIST: CC0402_25,CC0402_HD,0402_CC; HEIGHT: 0.55MM; MFG_NAME01: MURATA; MFG_PN01: GRM1555C1H120JZ01D; ROHS: Yes; Tolerance: 5%
C205 = CAP_NP: CAP CER 4.7UF 6.3V 10% X5R 0603; CAD_APPROVED: Yes; FPLIST: CC0603_OV,CC0603,0603_CC; HEIGHT: 0.95MM; MFG_NAME01: Murata; MFG_PN01: GRM188R60J475KE19D; ROHS: Yes; Tolerance: 10%
C206 = CAP_NP: CAP CER 0.47UF 6.3V 10% X5R 0402; AGILE_PN: 150-77952; CAD_APPROVED: Yes; FPLIST: CC0402_25,CC0402_HD,0402_CC; HEIGHT: 0.55MM; MFG_NAME01: Murata; MFG_PN01: GRM155R60J474KE19D; ROHS: Yes; Tolerance: 10%
C247-C249 C265 C266 = CAP_NP: CAP CER 47PF 50V 5% C0G 0402; CAD_APPROVED: YES; FPLIST: CC0402_25,CC0402_HD,0402_CC; HEIGHT: 0.56MM; MFG_NAME01: AVX; MFG_PN01: 04025A470JAT2A; ROHS: Yes; Tolerance: 5%
C250-C252 = CAP_NP: CAP CER 10PF 16V 0.25PF C0G 0402; CAD_APPROVED: Yes; FPLIST: CC0402_25,CC0402_HD,0402_CC; HEIGHT: 0.55MM; MFG_NAME01: MURATA; MFG_PN01: GRM1555C1H100JZ01D; ROHS: Yes; Tolerance: 0.25PF
C305 = CAP_NP: CAP CER 1UF 16V 10% X7R 0603; CAD_APPROVED: Yes; FPLIST: CC0603_OV,CC0603,0603_CC; HEIGHT: 0.84mm; MFG_NAME01: TAIYO YUDEN; MFG_PN01: EMK107B7105KA-T; ROHS: Yes; Tolerance: 10%
D7 D8 = LED: LED ULTRA-BRIGHT GREEN SMT 0603; AGILE_PN: 370-75077; CAD_APPROVED: YES; HEIGHT: 0.8MM; MFG_NAME01: LITE ON; MFG_PN01: LTST-C190KGKT; ROHS: Yes
J8 = USB_MINI_AB_RECEPTACLE: CON 1X5 USB_MINI_AB_RECEPTACLE RA SMT 0.65MM SP 105H AU; AGILE_PN: 211-78722; CAD_APPROVED: Yes; HEIGHT: 2.65MM; MFG_NAME01: Molex; MFG_PN01: 47589-0001; ROHS: Yes
L1 L5 L15 = INDUCTOR: IND FER BEAD 470OHM@100MHZ 500MA 25% 0603; AGILE_PN: 180-76158; CAD_APPROVED: Yes; FPLIST: IND_0603,0603_CC; HEIGHT: 0.95MM; MFG_NAME01: MURATA; MFG_PN01: BLM18EG471SN1D; ROHS: Yes; Tolerance: 25%
L34 = 42H171000: IND CHOKE USB2.0 90OHM@100MHz 500mA SMT 0805; AGILE_PN: 180-77702; CAD_APPROVED: Yes; HEIGHT: 1.65MM; MFG_NAME01: COILCRAFT; MFG_PN01: 0805USB-901MLC; PART_TYPE: CHOKE; ROHS: Yes
Q16-Q20 = MOSFET_N: TRAN NMOS SW 30V 270MA SC-70; AGILE_PN: 480-76278; CAD_APPROVED: Yes; HEIGHT: 1.0MM; MFG_NAME01: ON SEMICONDUCTOR; ROHS: Yes
R4 R5 R7 R8 = RES: RES MF 49.9 OHM 1/16W 1% 0402; AGILE_PN: 470-75360; CAD_APPROVED: Yes; FPLIST: RC0402_25,RC0402_HD,0402_CC; MFG_NAME01: KOA SPEER; MFG_PN01: RK73H1ETTP49R9F; ROHS: Yes; Tolerance: 1%
R6 R83 R84 R86-R92 R101 R102 R107 R206 = RES: RES MF ZERO OHM 1/16W 5% 0402; AGILE_PN: 470-75394; CAD_APPROVED: Yes; FPLIST: RC0402_25,RC0402_HD,RC0402_X2,0402_CC; MFG_NAME01: ROHM; MFG_PN01: MCR01MZPJ000; ROHS: Yes; Tolerance: 5%
R9 R104 R105 R127 R144 R152 R153 = RES: RES MF 4.70K 1/16W 1% 0402; CAD_APPROVED: Yes; FPLIST: RC0402_25,RC0402_HD,0402_CC; MFG_NAME01: VISHAY; MFG_PN01: CRCW04024K70FKED; ROHS: Yes; Tolerance: 1%
R10 R11 = RES: RES MF 270 OHM 1/16W 5% 0402; AGILE_PN: 470-30332; CAD_APPROVED: Yes; FPLIST: RC0402_25,RC0402_HD,0402_CC; MFG_NAME01: VISHAY INTERTECHNOLOGY; MFG_PN01: CRCW0402270RJNED; ROHS: Yes; Tolerance: 5%
R14 = RES: RES MF 10.0K 1/16W 1% 0402; AGILE_PN: 470-75416; ASSY_OPT: DNP; CAD_APPROVED: Yes; FPLIST: RC0402_25,RC0402_HD,0402_CC; MFG_NAME01: KOA SPEER; MFG_PN01: RK73H1ETTP1002F; ROHS: Yes; Tolerance: 1%
R15 = RES: RES MF 12.1K  1/16W 1% 0402; AGILE_PN: 470-30956; CAD_APPROVED: Yes; FPLIST: RC0402_25,RC0402_HD,0402_CC; MFG_NAME01: KOA SPEER; MFG_PN01: RK73H1ETTP1212F; ROHS: Yes; Tolerance: 1%
R47 R214 = RES: RES MF 1.0M 1/16W 5% 0402; AGILE_PN: 470-75642; CAD_APPROVED: Yes; FPLIST: RC0402_25,RC0402_HD,0402_CC; MFG_NAME01: VENKEL COMPANY; MFG_PN01: CR0402-16W-105JT; ROHS: Yes; Tolerance: 5%
R46 R68 R69 R211 = RES: RES MF 453 OHM 1/16W 1% 0402; AGILE_PN: 470-30804; CAD_APPROVED: Yes; FPLIST: RC0402_25,RC0402_HD,0402_CC; MFG_NAME01: KOA SPEER; MFG_PN01: RK73H1ETTP4530F; ROHS: Yes; Tolerance: 1%
R180-R188 R193-R198 = RES: RES MF 10 OHM 1/16W 5% 0402; CAD_APPROVED: Yes; FPLIST: RC0402_25,RC0402_HD,0402_CC; MFG_NAME01: Stackpole Electronics; MFG_PN01: RMCF0402JT10R0; ROHS: Yes; Tolerance: 5%
R208 = RES: RES MF ZERO OHM 1/10W 1% 0603; AGILE_PN: 470-80217; CAD_APPROVED: Yes; FPLIST: RC0603_OV,RC0603,R603-X2,0603_CC; MFG_NAME01: MULTICOMP; MFG_PN01: MC0603SAF0000T5E; ROHS: Yes; Tolerance: 1%
T1 = HFJ11-2450E-L12RL: CON 8 RJ-45 10/100BASE-TX SHLD RA TH G/Y LEDS 50MIL SP 537H AU; AGILE_PN: 210-75881; CAD_APPROVED: Yes; HEIGHT: 13.84 MM; MFG_NAME01: HALO ELECTRONICS; ROHS: Yes
TP15 TP16 = Test_pad: TEST PAD 35 MIL ROUND SMT; NO PART TO ORDER; AGILE_PN: 510-75219; CAD_APPROVED: Yes; HEIGHT: 0.1 MM; ROHS: Yes
U3 = LAN8720A-QFN24: IC XCVR ETHERNET 1.6-3.6V QFN24; AGILE_PN: 312-79651; CAD_APPROVED: Yes; HEIGHT: 1MM; MFG_NAME01: SMSC; MFG_PN01: LAN8720A-CP-TR; ROHS: Yes
U34 = USB2SERA10CFK: IC XCVR USB TO UART CONV 12MBPS 3-5V QFN24; AGILE_PN: 312-80126; CAD_APPROVED: Yes; HEIGHT: 1MM; MFG_NAME01: FREESCALE SEMICONDUCTOR; ROHS: Yes
Y8 = CRYSTAL_JXS63: XTAL 12MHZ 12PF -- 3.2X2.5MM SMT; CAD_APPROVED: Yes; HEIGHT: 0.7MM; MFG_NAME01: AKER TECHNOLOGY CO., LTD; MFG_PN01: C3E-12.000-12-3030-X; ROHS: Yes
C254-C264 C289-C291 = CAP_NP: CAP CER 47PF 16V 5% C0G 0402; CAD_APPROVED: YES; FPLIST: CC0402_25,CC0402_HD,0402_CC; HEIGHT: 0.56MM; MFG_NAME01: AVX; MFG_PN01: 04025A470JAT2A; ROHS: Yes; Tolerance: 5%
D3 D35-D42 = LED_DUAL_SEP2_RG: LED DUAL GRN/RED 30MA SMT; AGILE_PN: 370-75742; CAD_APPROVED: Yes; HEIGHT: 0.65MM; MFG_NAME01: LITE ON; MFG_PN01: LTST-C195KGJRKT; ROHS: Yes
FL1-FL8 = EMIFILTER_NFA18SD: FILTER EMI 4 LINE 180MHZ 10V 0603; CAD_APPROVED: Yes; HEIGHT: 0.6 MM; MFG_NAME01: MURATA; MFG_PN01: NFA18SL307V1A45L; ROHS: Yes
J13 = QSH060: CON 2X60 SKT SMT 0.5MM SP AU; AGILE_PN: 211-75241; CAD_APPROVED: Yes; HEIGHT: 3.25 MM; MFG_NAME01: SAMTEC; ROHS: Yes
R85 R100 R106 R110 R207 = RES: RES MF ZERO OHM 1/16W 5% 0402; AGILE_PN: 470-75394; ASSY_OPT: DNP; CAD_APPROVED: Yes; FPLIST: RC0402_25,RC0402_HD,RC0402_X2,0402_CC; MFG_NAME01: ROHM; MFG_PN01: MCR01MZPJ000; ROHS: Yes; Tolerance: 5%
R93 = RES: RES MF ZERO OHM 1/10W -- 0603; CAD_APPROVED: Yes; FPLIST: RC0603_OV,RC0603,R603-X2,0603_CC; MFG_NAME01: Yageo; MFG_PN01: RC0603JR-070RL; ROHS: Yes; Tolerance: 1%
R27 R124 R126 R140 R151 = RES: RES MF 47K 1/16W 5% 0402; CAD_APPROVED: Yes; FPLIST: RC0402_25,RC0402_HD,0402_CC; MFG_NAME01: VISHAY; MFG_PN01: CRCW040247K0JNED; ROHS: Yes; Tolerance: 5%
RN6 RN7 = RES_ISO8_SINGLE: RNET ISO 8 470OHM 1/16W 5% 0402X8; AGILE_PN: 470-79899; CAD_APPROVED: Yes; FPLIST: RCA8_16,RCA8_16; MFG_NAME01: Panasonic; MFG_PN01: EXB2HV471JV; ROHS: Yes; Tolerance: 5%
SW5 SW6 SW8 = SW2_SPST_PB: SW SPDT 100MILLIAMPS@12VDC; AGILE_PN: 510-75076; CAD_APPROVED: Yes; HEIGHT: 2MM; MFG_NAME01: ITT CANNON; MFG_PN01: SDS001; ROHS: Yes
SW7 = EDGE_MOUNT_PB_SW_2: SW SPST NO PB 2.2N SIDE 12V 50MA SMT; AGILE_PN: 510-76838; CAD_APPROVED: Yes; HEIGHT: 1.95MM; MFG_NAME01: PANASONIC; ROHS: Yes
U1 = PCIMX287DJM4A_MAPBGA_289P: IC MCU ARM926EJ-S 128KB RAM 128KB ROM 454MHZ MAPBGA289; AGILE_PN: 330-76586; CAD_APPROVED: Yes; HEIGHT: 1.37MM; MFG_NAME01: FREESCALE SEMICONDUCTOR; ROHS: Yes
U5 = K9F2G08U0A_48P: IC MEM NAND FLASH 512MX8 2.7-3.6V TSOP48; AGILE_PN: 334-75698; CAD_APPROVED: Yes; HEIGHT: 1.2MM; MFG_NAME01: MICRON; MFG_PN01: MT29F4G08ABADAWP:D; ROHS: Yes
C73 = CAP_NP: CAP CER 10UF 6.3V 10% X5R 0805; CAD_APPROVED: Yes; FPLIST: CC0805_OV,CC0805,0805_CC; HEIGHT: 1.45 MM; MFG_NAME01: SAMSUNG; MFG_PN01: CL21A106KPFNNNE; ROHS: Yes; Tolerance: 10%

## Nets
3V3_DEBUG: C205.1 C206.1 U34.16(VUSB33) U34.17(VUSB33_MON)
3V3_GATED: C29.1 C249.1 C250.1 L1.2 R9.1 R12.1 R13.2 R14.2 U3.9(VDDIO) ; also on sheet 11 12 13 15 16
3V3_MAIN: L15.2 R212.1 ; also on sheet 14 16
5V: C256.1 C258.1 C259.1 C262.1 C290.1 J13.2 J13.4 J13.7 J13.8 J13.11 J13.13 J13.39 J13.41 ; also on sheet 16
5V_DEBUG: C35.1 C134.1 L5.1 Q17.1(GATE) Q18.1(GATE) Q19.1(GATE) Q20.1(GATE) R19.1 R68.1 R69.1 R214.2 U34.11(VDD)
5V_MAIN_PRESENT: U1.D3(SSP2_SS1/SSP2_D4/SSP2_D1/USB1_OVERCURRENT/GPIO2_20) ; also on sheet 16 17
GND: C1.2 C2.2 C3.2 C4.2 C5.2 C6.2 C7.2 C8.2 C9.2 C10.2 C11.2 C12.2 C13.2 C14.2 C15.2 C16.2 C17.2 C18.2 C19.2 C20.2 C21.2 C22.2 C23.2 C25.2 C26.2 C27.2 C28.2 C29.2 C30.2 C31.2 C32.2 C33.2 C34.2 C35.2 C51.2 C52.2 C57.2 C59.2 C60.2 C62.2 C63.2 C64.2 C65.2 C66.2 C67.2 C69.2 C70.2 C71.2 C72.2 C73.2 C74.2 C75.2 C76.2 C77.2 C78.2 C79.2 C80.2 C81.2 C83.2 C84.2 C86.2 C87.2 C88.2 C89.2 C90.2 C91.2 C92.2 C93.2 C94.2 C95.2 C96.2 C97.2 C98.2 C134.2 C148.2 C149.2 C205.2 C206.2 C245.2 C246.2 C247.2 C248.2 C249.2 C250.2 C251.2 C252.2 C254.2 C255.2 C256.2 C257.2 C258.2 C259.2 C260.2 C261.2 C262.2 C263.2 C264.2 C265.2 C266.2 C289.2 C290.2 C291.2 C296.2 FL1.1(GND1) FL1.2(GND2) FL2.1(GND1) FL2.2(GND2) FL3.1(GND1) FL3.2(GND2) FL4.1(GND1) FL4.2(GND2) FL5.1(GND1) FL5.2(GND2) FL6.1(GND1) FL6.2(GND2) FL7.1(GND1) FL7.2(GND2) FL8.1(GND1) FL8.2(GND2) J13.6 J13.12 J13.18 J13.23 J13.24 J13.30 J13.36 J13.42 J13.48 J13.54 J13.60 J13.93 J13.103 J13.SH1 J13.SH2 J13.SH3 J13.SH4 J13.SH5 J13.SH6 J13.SH7 J13.SH8 Q16.2(SOURCE) R3.2 R11.2 R15.2 R16.1 R18.1 R27.2 R58.2 R208.1 R214.1 SW5.2 SW6.1 SW7.2 SW7.4 SW8.1 T1.7(NC) T1.8(GND) T1.13(GND) T1.14(GND) U1.A1(VSS1) U1.A9(VSS2) U1.B7(VSS3) U1.B11(VSSA2_A) U1.B13(VSSA1) U1.C16(VSS4) U1.E5(VSS5) U1.E15(VSS6) U1.F14(VSSIO_EMI10) U1.F16(VSSIO_EMI9) U1.H3(VSS7) U1.H9(VSS8) U1.H10(VSS9) U1.H11(VSS10) U1.H12(VSS11) U1.H14(VSSIO_EMI8) U1.H16(VSS12) U1.J11(VSS13) U1.J12(VSS14) U1.J15(VSS15) U1.K9(VSS16) U1.K10(VSS17) U1.K11(VSS18) U1.L10(VSS19) U1.L11(VSS20) U1.L12(VSSIO_EMI7) U1.M14(VSS21) U1.M16(VSSIO_EMI6) U1.N4(VSS22) U1.P14(VSSIO_EMI4) U1.P16(VSSIO_EMI5) U1.R10(VSSIO_EMI_11) U1.R12(VSSIO_EMI1) U1.T14(VSSIO_EMI3) U1.U1(VSS23) U1.U17(VSSIO_EMI2) U2.A3(VSS1) U2.A7(VSSQ2) U2.B2(VSSQ3) U2.B8(VSSQ1) U2.D2(VSSQ4) U2.D8(VSSQ5) U2.E3(VSS2) U2.E7(VSSQ6) U2.F2(VSSQ7) U2.F8(VSSQ8) U2.H2(VSSQ9) U2.H8(VSSQ10) U2.J3(VSS3) U2.J7(VSSDL) U2.N1(VSS4) U2.P9(VSS5) U3.25(VSS) U5.13(VSS1) U5.36(VSS2) U34.13(VSS) U34.23(VSSOSC) U34.25(EP) Y8.2(GND) Y8.4(GND) ; also on sheet 10 11 12 13 14 15 16 17
VBUS_OTG: C254.1 R93.2 ; also on sheet 14 17
VDD_1V5: C291.1 J13.111 J13.113 J13.115
BT_ACTIVE: R101.1 ; also on sheet 13
BUTTON_1: R127.1 R151.1 U1.B5(SSP0_DATA4/SSP2_D0/GPIO2_4)
BUTTON_2: R124.1 R144.1 U1.C5(SSP0_DATA5/SSP2_D3/GPIO2_5)
BUTTON_3: R140.1 R153.2 U1.D5(SSP0_DATA6/SSP2_CMD/GPIO2_6)
BUTTON_4: R126.1 R152.2 U1.D10(SSP0_DETECT/GPIO2_9)
DCDC_VDDA_1V8: C1.1 C2.1 C3.1 C4.1 C5.1 C6.1 C7.1 C8.1 C9.1 C10.1 C11.1 C12.1 C13.1 C14.1 C15.1 C16.1 C17.1 C18.1 C19.1 C20.1 C21.1 C22.1 C23.1 C24.1 C74.1 C75.1 C76.1 C77.1 C78.1 C79.1 C80.1 C81.1 C83.1 C84.1 C86.1 C87.1 C88.1 C89.1 C90.1 C91.1 C92.1 C93.1 C94.1 C95.1 C98.1 C245.1 C246.1 C257.1 C261.1 C264.1 J13.1 J13.17 J13.19 J13.25 R2.1 U1.C13(VDDA1) U1.F8(VDDIO18_0) U1.F9(VDDIO18_1) U1.G8(VDDIO18_2) U1.G9(VDDIO18_3) U1.G13(VDDIO_EMI_8_1) U1.G15(VDDIO_EMI_8_2) U1.G17(VDDIO_EMI_8_3) U1.J13(VDDIO_EMIQ2) U1.K15(VDDIO_EMIQ1) U1.L13(VDDIO_EMI_7) U1.M10(VDDIO_EMI_0) U1.M11(VDDIO_EMI_3_1) U1.M12(VDDIO_EMI_3_2) U1.N13(VDDIO_EMI_3_3) U1.N15(VDDIO_EMI_6) U1.P11(VDDIO_EMI_1) U1.R13(VDDIO_EMI_3_4) U1.R15(VDDIO_EMIQ0) U2.A1(VDD1) U2.A9(VDDQ6) U2.C1(VDDQ2) U2.C3(VDDQ3) U2.C7(VDDQ4) U2.C9(VDDQ5) U2.E1(VDD2) U2.E9(VDDQ1) U2.G1(VDDQ7) U2.G3(VDDQ8) U2.G7(VDDQ9) U2.G9(VDDQ10) U2.J1(VDDL) U2.J9(VDD3) U2.M9(VDD4) U2.R1(VDD5) ; also on sheet 17
DCDC_VDDD_1V2: C57.1 C59.1 C60.1 C62.1 C63.1 U1.F10(VDDD0) U1.F11(VDDD1) U1.F12(VDDD2) U1.G10(VDDD3) U1.G11(VDDD4) U1.G12(VDDD5) U1.K12(VDDD6) ; also on sheet 17
DCDC_VDDIO_3V3: C51.1 C52.1 C64.1 C65.1 C66.1 C67.1 C69.1 C70.1 C71.1 C72.1 C73.1 C96.1 C97.1 C255.1 C260.1 C265.1 C266.1 J13.5 J13.45 J13.47 J13.49 R17.1 R25.1 R26.1 R104.1 R105.1 R124.2 R126.2 R140.2 R151.2 R213.2 U1.A7(VDDIO33_8) U1.E6(VDDIO33_0) U1.E16(VDDIO33_7) U1.G3(VDDIO33_1) U1.H8(VDDIO33_5_1) U1.J8(VDDIO33_5_2) U1.J9(VDDIO33_5_3) U1.J10(VDDIO33_5_4) U1.N3(VDDIO33_4) U1.N17(VDDIO33_EMI) U5.12(VCC1) U5.37(VCC2) ; also on sheet 10 12 13 14 15 16 17
DDR2_A0: U1.U15(EMI_A00) U2.M8(A0)
DDR2_A1: U1.U12(EMI_A01) U2.M3(A1)
DDR2_A2: U1.U14(EMI_A02) U2.M7(A2)
DDR2_A3: U1.T11(EMI_A03) U2.N2(A3)
DDR2_A4: U1.U10(EMI_A04) U2.N8(A4)
DDR2_A5: U1.R11(EMI_A05) U2.N3(A5)
DDR2_A6: U1.R9(EMI_A06) U2.N7(A6)
DDR2_A7: U1.N11(EMI_A07) U2.P2(A7)
DDR2_A8: U1.U9(EMI_A08) U2.P8(A8)
DDR2_A9: U1.P10(EMI_A09) U2.P3(A9)
DDR2_A10: U1.U13(EMI_A10) U2.M2(A10)
DDR2_A11: U1.T10(EMI_A11) U2.P7(A11)
DDR2_A12: U1.U11(EMI_A12) U2.R2(A12)
DDR2_A13: U1.T9(EMI_A13) U2.R8(NC/A13)
DDR2_A14: U1.N10(EMI_A14) U2.R3(NC/A14)
DDR2_BA0: U1.T16(EMI_BA0) U2.L2(BA0)
DDR2_BA1: U1.T12(EMI_BA1) U2.L3(BA1)
DDR2_BA2: U1.N12(EMI_BA2) U2.L1(NC/BA2)
DDR2_CAS_B: U1.U16(~{EMI_CAS}) U2.L7(CAS#)
DDR2_CKE: R58.1 U1.T13(EMI_CKE) U2.K2(CKE)
DDR2_CLK: R1.1 U1.L17(EMI_CLK) U2.J8(CK)
DDR2_CLK_B: R1.2 U1.L16(~{EMI_CLK}) U2.K8(CK#)
DDR2_CS_B: U1.P12(~{EMI_CE0}) U2.L8(CS#)
DDR2_D00: U1.N16(EMI_D00) U2.H1(DQ4)
DDR2_D01: U1.M13(EMI_D01) U2.G2(DQ1)
DDR2_D02: U1.P15(EMI_D02) U2.H3(DQ3)
DDR2_D03: U1.N14(EMI_D03) U2.F1(DQ6)
DDR2_D04: U1.P13(EMI_D04) U2.H7(DQ2)
DDR2_D05: U1.P17(EMI_D05) U2.H9(DQ5)
DDR2_D06: U1.L14(EMI_D06) U2.F9(DQ7)
DDR2_D07: U1.M17(EMI_D07) U2.G8(DQ0)
DDR2_D08: U1.G16(EMI_D08) U2.C8(DQ8)
DDR2_D09: U1.H15(EMI_D09) U2.D7(DQ10)
DDR2_D10: U1.G14(EMI_D10) U2.C2(DQ9)
DDR2_D11: U1.J14(EMI_D11) U2.D3(DQ11)
DDR2_D12: U1.H13(EMI_D12) U2.D1(DQ12)
DDR2_D13: U1.H17(EMI_D13) U2.D9(DQ13)
DDR2_D14: U1.F13(EMI_D14) U2.B1(DQ14)
DDR2_D15: U1.F17(EMI_D15) U2.B9(DQ15)
DDR2_DQM0: U1.M15(EMI_DQM0) U2.F3(LDM)
DDR2_DQM1: U1.F15(EMI_DQM1) U2.B3(UDM)
DDR2_DQS0: U1.K17(EMI_DQS0) U2.F7(LDQS)
DDR2_DQS0_B: U1.K16(~{EMI_DQS0}) U2.E8(LDQSn)
DDR2_DQS1: U1.J17(EMI_DQS1) U2.B7(UDQS)
DDR2_DQS1_B: U1.J16(~{EMI_DQS1}) U2.A8(UDQSn)
DDR2_ODT0: U1.R17(EMI_ODT0) U2.K9(ODT)
DDR2_OPEN: U1.K14(EMI_DDR_OPEN) U1.L15(EMI_DDR_OPEN_FB)
DDR2_RAS_B: U1.R16(~{EMI_RAS}) U2.K7(RAS#)
DDR2_VREF: C24.2 C25.1 R2.2 R3.1 U1.K13(EMI_VREF1) U1.R14(EMI_VREF0) U2.J2(VREF)
DDR2_WE_B: U1.T15(~{EMI_WE}) U2.K3(WE#)
DEBUG_GND: C305.2 J8.5(P5) J8.S1(SHLD1) J8.S2(SHLD2) J8.S3(SHLD3) J8.S4(SHLD4) R208.2
DUART_RX: Q19.2(SOURCE) R213.1 U1.K7(PWM0/I2C1_SCL/DUART_RX/GPIO3_16)
DUART_TX: Q17.2(SOURCE) U1.L7(PWM1/I2C1_SDA/DUART_TX/GPIO3_17)
ENET_CLKO: R180.1 U1.E2(ENET_CLK/GPIO4_16)
ENET_INT: R13.1 U3.14(I~{NT}/REFCLKO) ; also on sheet 15
ENET_MDC: R182.1 U1.G4(ENET0_MDC/~{GPMI_CE4}/SAIF0_SDATA1/GPIO4_0)
ENET_MDIO: R181.1 U1.H4(ENET0_MDIO/~{GPMI_CE5}/SAIF0_SDATA2/GPIO4_1)
ENET_RESET_B: R12.2 U3.15(~{RST}) ; also on sheet 15
ENET_RXD0: R183.1 U1.H1(ENET0_RXD0/~{GPMI_CE7}/SAIF1_SDATA2/GPIO4_3)
ENET_RXD1: R184.1 U1.H2(ENET0_RXD1/GPMI_READY4/GPIO4_4)
ENET_RXEN: R185.1 U1.E4(ENET0_RX_EN/~{GPMI_CE6}/SAIF1_SDATA1/GPIO4_2)
ENET_TXD0: R186.1 U1.F1(ENET0_TXD0/GPMI_READY6/GPIO4_7)
ENET_TXD1: R187.1 U1.F2(ENET0_TXD1/GPMI_READY7/GPIO4_8)
ENET_TXEN: R188.1 U1.F4(ENET0_TX_EN/GPMI_READY5/GPIO4_6)
ETH_RXN: R5.2 T1.6(RD-) U3.22(RXN)
ETH_RXP: R4.2 T1.3(RD+) U3.23(RXP)
ETH_TXN: R8.2 T1.2(TD-) U3.20(TXN)
ETH_TXP: R7.2 T1.1(TD+) U3.21(TXP)
FEC_A3V3: C26.1 C27.1 C28.1 C30.1 C247.1 C248.1 C251.1 C252.1 L1.1 R4.1 R5.1 R6.1 R7.1 R8.1 R10.2 U3.1(VDD2A) U3.19(VDD1A)
I2C_SCL: R104.2 U1.C7(I2C0_SCL/TIMROT_ROTARYA/DUART_RX/GPIO3_24) ; also on sheet 10 12 14 15
I2C_SCL_IO_EXP: J13.31
I2C_SDA: R105.2 U1.D8(I2C0_SDA/TIMROT_ROTARYB/DUART_TX/GPIO3_25) ; also on sheet 10 12 14 15
I2C_SDA_IO_EXP: J13.29
IO_EXP_INT_B: U1.N8(GPMI_RDY1/SSP1_CMD/GPIO0_21) ; also on sheet 15
ISM_LED: R206.1 ; also on sheet 10
LAN_LED_G: T1.10(GLED-) U3.2(LED2/I~{NTSEL})
LAN_LED_Y: T1.11(YLED+) U3.3(LED1/REGOFF)
LCD_BL_PWM: FL1.4(IN(OUT)2) U1.E10(PWM4/GPIO3_29)
LCD_BL_PWM_EMI: FL1.8(OUT(IN)2) J13.112 R92.2
LCD_CARD_PRESENT: J13.83 ; also on sheet 15
LCD_CS: FL8.6(IN(OUT)4) U1.P5(LCD_CS/LCD_ENABLE/GPIO1_27)
LCD_CS_CON: J13.105 R83.1
LCD_CS_EMI: FL8.10(OUT(IN)4) R83.2 R84.2
LCD_D0: FL7.3(IN(OUT)1) U1.K2(LCD_D00/ETM_DA0/GPIO1_0) ; also on sheet 16
LCD_D0_EMI: FL7.7(OUT(IN)1) J13.62
LCD_D1: FL7.4(IN(OUT)2) U1.K3(LCD_D01/ETM_DA1/GPIO1_1) ; also on sheet 16
LCD_D1_EMI: FL7.8(OUT(IN)2) J13.64
LCD_D2: FL7.5(IN(OUT)3) U1.L2(LCD_D02/ETM_DA2/GPIO1_2) ; also on sheet 16
LCD_D2_EMI: FL7.9(OUT(IN)3) J13.66
LCD_D3: FL7.6(IN(OUT)4) U1.L3(LCD_D03/ETM_DA3/ETM_DA8/GPIO1_3) ; also on sheet 16
LCD_D3_EMI: FL7.10(OUT(IN)4) J13.68
LCD_D4: FL6.3(IN(OUT)1) U1.M2(LCD_D04/ETM_DA4/ETM_DA9/GPIO1_4) ; also on sheet 16
LCD_D4_EMI: FL6.7(OUT(IN)1) J13.70
LCD_D5: FL6.4(IN(OUT)2) U1.M3(LCD_D05/ETM_DA5/GPIO1_5)
LCD_D5_EMI: FL6.8(OUT(IN)2) J13.72
LCD_D6: FL6.5(IN(OUT)3) Q16.1(GATE) R212.2 U1.N2(LCD_D06/ETM_DA6/GPIO1_6)
LCD_D6_EMI: FL6.9(OUT(IN)3) J13.74
LCD_D7: FL6.6(IN(OUT)4) R46.1 U1.P1(LCD_D07/ETM_DA7/GPIO1_7)
LCD_D7_EMI: FL6.10(OUT(IN)4) J13.76
LCD_D8: FL5.3(IN(OUT)1) RN7.1(A) U1.P2(LCD_D08/ETM_DA8/ETM_DA3/GPIO1_8)
LCD_D8_EMI: FL5.7(OUT(IN)1) J13.78
LCD_D9: FL5.4(IN(OUT)2) RN7.2(A) U1.P3(LCD_D09/ETM_DA9/ETM_DA4/GPIO1_9)
LCD_D9_EMI: FL5.8(OUT(IN)2) J13.80
LCD_D10: FL5.5(IN(OUT)3) RN7.3(A) U1.R1(LCD_D10/ETM_DA10/GPIO1_10)
LCD_D10_EMI: FL5.9(OUT(IN)3) J13.82
LCD_D11: FL5.6(IN(OUT)4) RN7.4(A) U1.R2(LCD_D11/ETM_DA11/GPIO1_11)
LCD_D11_EMI: FL5.10(OUT(IN)4) J13.84
LCD_D12: FL4.3(IN(OUT)1) RN7.5(A) U1.T1(LCD_D12/ETM_DA12/GPIO1_12)
LCD_D12_EMI: FL4.7(OUT(IN)1) J13.86
LCD_D13: FL4.4(IN(OUT)2) RN7.6(A) U1.T2(LCD_D13/ETM_DA13/GPIO1_13)
LCD_D13_EMI: FL4.8(OUT(IN)2) J13.88
LCD_D14: FL4.5(IN(OUT)3) RN7.7(A) U1.U2(LCD_D14/ETM_DA14/GPIO1_14)
LCD_D14_EMI: FL4.9(OUT(IN)3) J13.90
LCD_D15: FL4.6(IN(OUT)4) RN7.8(A) U1.U3(LCD_D15/ETM_DA15/GPIO1_15)
LCD_D15_EMI: FL4.10(OUT(IN)4) J13.92
LCD_D16: FL3.3(IN(OUT)1) RN6.1(A) U1.T3(LCD_D16/ETM_DA7/GPIO1_16)
LCD_D16_EMI: FL3.7(OUT(IN)1) J13.94
LCD_D17: FL3.4(IN(OUT)2) R207.1 U1.R3(LCD_D17/ETM_DA6/GPIO1_17)
LCD_D17_EMI: FL3.8(OUT(IN)2) J13.96
LCD_D18: FL3.5(IN(OUT)3) RN6.3(A) U1.U4(LCD_D18/ETM_DA5/GPIO1_18)
LCD_D18_EMI: FL3.9(OUT(IN)3) J13.98
LCD_D19: FL3.6(IN(OUT)4) R107.1 U1.T4(LCD_D19/ETM_DA4/GPIO1_19)
LCD_D19_EMI: FL3.10(OUT(IN)4) J13.100
LCD_D20: FL2.3(IN(OUT)1) RN6.5(A) U1.R4(LCD_D20/ENET1_1588_EVENT2_OUT/ETM_DA3/GPIO1_20)
LCD_D20_EMI: FL2.7(OUT(IN)1) J13.102
LCD_D21: FL2.4(IN(OUT)2) R100.1 U1.U5(LCD_D21/ENET1_1588_EVENT2_IN/ETM_DA2/GPIO1_21)
LCD_D21_EMI: FL2.8(OUT(IN)2) J13.104
LCD_D22: FL2.5(IN(OUT)3) RN6.7(A) U1.T5(LCD_D22/ENET1_1588_EVENT3_OUT/ETM_DA1/GPIO1_22)
LCD_D22_EMI: FL2.9(OUT(IN)3) J13.106
LCD_D23: FL2.6(IN(OUT)4) R106.1 U1.R5(LCD_D23/ENET1_1588_EVENT3_IN/ETM_DA0/GPIO1_23)
LCD_D23_EMI: FL2.10(OUT(IN)4) J13.108
LCD_DOTCLK: J13.43 R87.1
LCD_ENABLE: J13.116 R84.1
LCD_HSYNC: J13.114 R89.1
LCD_PWR_EN: J13.79 U1.M6(LCD_RESET/LCD_VSYNC/GPIO3_30)
LCD_RD_E: FL8.5(IN(OUT)3) U1.P4(LCD_RD_E/LCD_VSYNC/ETM_TCTL/GPIO1_24)
LCD_RD_E_CON: R85.2 R90.1
LCD_RD_E_EMI: FL8.9(OUT(IN)3) R90.2 R91.2
LCD_RS: FL8.3(IN(OUT)1) U1.M4(LCD_RS/LCD_DOTCLK/GPIO1_26)
LCD_RS_CON: J13.119 R86.1
LCD_RS_EMI: FL8.7(OUT(IN)1) R86.2 R87.2
LCD_RW_B: FL8.4(IN(OUT)2) U1.K1(LCD_WR_RWN/LCD_HSYNC/ETM_TCLK/GPIO1_25)
LCD_RW_B_EMI: FL8.8(OUT(IN)2) R88.2 R89.2
LCD_VSYNC: J13.110 R91.1
LCD_WR_RWN_CON: J13.109 R88.1
LI-ION_BATTERY: C263.1 C289.1 J13.65 J13.67 J13.69 J13.71 ; also on sheet 16 17
LRADC2: J13.99 ; also on sheet 17
LRADC3: J13.95 ; also on sheet 17
LRADC4: J13.101 ; also on sheet 17
LRADC5: J13.97 ; also on sheet 17
LRADC6: J13.38 ; also on sheet 17
MODEM_VBUS_EN: U1.D7(SPDIF/ENET1_RX_ER/GPIO3_27) ; also on sheet 14
NAND_ALE: U1.P6(GPMI_ALE/SSP3_D1/SSP3_D4/GPIO0_26) U5.17(ALE)
NAND_CE_B: R25.2 U1.N7(~{GPMI_CE0}/SSP3_D0/GPIO0_16) U5.9(~{CE})
NAND_CLE: U1.P7(GPMI_CLE/SSP3_D2/SSP3_D5/GPIO0_27) U5.16(CLE)
NAND_DAT0: U1.U8(GPMI_D00/SSP1_D0/GPIO0_0) U5.29(IO0)
NAND_DAT1: U1.T8(GPMI_D01/SSP1_D1/GPIO0_1) U5.30(IO1)
NAND_DAT2: U1.R8(GPMI_D02/SSP1_D2/GPIO0_2) U5.31(IO2)
NAND_DAT3: U1.U7(GPMI_D03/SSP1_D3/GPIO0_3) U5.32(IO3)
NAND_DAT4: U1.T7(GPMI_D04/SSP1_D4/GPIO0_4) U5.41(IO4)
NAND_DAT5: U1.R7(GPMI_D05/SSP1_D5/GPIO0_5) U5.42(IO5)
NAND_DAT6: U1.U6(GPMI_D06/SSP1_D6/GPIO0_6) U5.43(IO6)
NAND_DAT7: U1.T6(GPMI_D07/SSP1_D7/GPIO0_7) U5.44(IO7)
NAND_RB_B: R26.2 U1.N6(GPMI_RDY0/SSP1_CARD_DETECT/USB0_ID/GPIO0_20) U5.7(READY/~{BUSY})
NAND_RE_B: U1.R6(~{GPMI_RD}/SSP3_SCK/GPIO0_24) U5.8(~{RE})
NAND_WP_B: R27.1 U1.L9(~{GPMI_RESET}/SSP3_CMD/GPIO0_28) U5.19(~{WP})
NAND_WR_B: U1.P8(~{GPMI_WR}/SSP1_SCK/GPIO0_25) U5.18(~{WE})
RXER/PHYAD0: R14.1 R16.2 U3.10(RXER/PHYAD0)
SAIF0_BITCLK: U1.F7(SAIF0_BITCLK/PWM_5/AUART4_RX/GPIO3_22) ; also on sheet 12
SAIF0_DIN: U1.E8(SAIF1_SDATA0/PWM_7/SAIF0_SDATA1/GPIO3_26) ; also on sheet 12
SAIF0_DOUT: U1.E7(SAIF0_SDATA0/PWM_6/AUART4_TX/GPIO3_23) ; also on sheet 12
SAIF0_LRCLK: U1.G6(SAIF0_LRCLK/PWM_4/AUART4_RTS/GPIO3_21) ; also on sheet 12
SAIF0_MCLK: U1.G7(SAIF0_MCLK/PWM_3/AUART4_CTS/GPIO3_20) ; also on sheet 12
SPI2_MISO: U1.B3(SSP2_MISO/SSP2_D0/AUART3_RX/SAIF1_SDATA1/GPIO2_18) U1.B4(SSP0_DATA7/SSP2_SCK/GPIO2_7) ; also on sheet 15
SPI2_MOSI: U1.C3(SSP2_MOSI/SSP2_CMD/AUART2_TX/SAIF0_SDATA2/GPIO2_17) ; also on sheet 15
SPI2_SCK: U1.A3(SSP2_SCK/AUART2_RX/SAIF0_SDATA1/GPIO2_16) ; also on sheet 15
SPI2_SS: U1.C4(SSP2_SS0/SSP2_D3/AUART3_TX/SAIF1_SDATA2/GPIO2_19) ; also on sheet 15
TOUCH_RESET: J13.33 R92.1
UART0_CTS: U1.J6(AUART0_CTS/AUART4_RX/DUART_RX/GPIO3_2) ; also on sheet 13
UART0_RTS: U1.J7(AUART0_RTS/AUART4_TX/DUART_TX/GPIO3_3) ; also on sheet 13
UART0_RX: U1.G5(AUART0_RX/I2C0_SCL/DUART_CTS/GPIO3_0) ; also on sheet 13
UART0_TX: U1.H5(AUART0_TX/I2C0_SDA/DUART_RTS/GPIO3_1) ; also on sheet 13
UART1_RX: U1.L4(AUART1_RX/SSP2_CARD_DETECT/PWM_0/GPIO3_4) ; also on sheet 11
UART1_TX: U1.K4(AUART1_TX/SSP3_CARD_DETECT/PWM_1/GPIO3_5) ; also on sheet 11
USB0_ID: R17.2 U1.K8(PWM2/USB0_ID/USB1_OVERCURRENT/GPIO3_18) ; also on sheet 17
USB2SER_RX: Q18.2(SOURCE) U34.19(RXD)
USB2SER_TX: Q20.2(SOURCE) U34.20(TXD)
USB_DEBUG_DM: L34.1 U34.14(USBDN)
USB_DEBUG_DP: L34.4 U34.15(USBDP)
USB_EXTAL: C148.1 R47.2 U34.22(EXTAL) Y8.3
USB_XTAL: C149.1 R47.1 U34.21(XTAL) Y8.1
USBOTG_OC: U1.D4(SSP2_SS2/SSP2_D5/SSP2_D2/USB0_OVERCURRENT/GPIO2_21) ; also on sheet 14
WIFI_SDIO_CLK: R193.2 ; also on sheet 13
WIFI_SDIO_CMD: R194.2 ; also on sheet 13
WIFI_SDIO_D0: R195.2 ; also on sheet 13
WIFI_SDIO_D1: R196.2 ; also on sheet 13
WIFI_SDIO_D2: R197.2 ; also on sheet 13
WIFI_SDIO_D3: R198.2 ; also on sheet 13
WLAN_ACTIVE: R110.1 ; also on sheet 13
ZIGBEE_GPIO: U1.E9(PWM3/GPIO3_28) ; also on sheet 11
ZIGBEE_LED: R102.1 ; also on sheet 11
N20183643: R9.2 R181.2 U3.12(MDIO)
N20200163: C31.1 R6.2 T1.4(CT1) T1.5(CT2)
N20766165: R15.1 U3.24(RBIAS)
N20769333: C32.1 C33.1 U3.6(VDDCR)
N28745352: J13.73 J13.75 J13.77 R93.1
N28745357: J13.117 R85.1
N28753815: D7.C(CATHODE) U34.7(UART_LED)
N28753820: D8.C(CATHODE) U34.5(USB_LED)
N28753851: D7.A(ANODE) R68.2
N28753854: D8.A(ANODE) R69.2
N28755364: C34.1 R19.2 U34.2(~{RESET})
N28758461: C305.1 J8.1(P1) L5.2
N28758635: R18.2 U34.10(CTS)
N28759486: TP15.1(Pin1) U34.1(~{RESUME})
N28759489: TP16.1(Pin1) U34.3(~{SUSPEND})
N28774283: J8.2(P2) L34.2
N28774290: J8.3(P3) L34.3
N28858706: R144.2 SW5.1
N28858725: R127.2 SW7.1 SW7.3
N28859319: R153.1 SW8.2
N28952872: C296.1 D3.1(ANODE2) D3.2(ANODE1) D35.1(ANODE2) D35.2(ANODE1) D36.1(ANODE2) D36.2(ANODE1) D37.1(ANODE2) D37.2(ANODE1) D38.1(ANODE2) D38.2(ANODE1) D39.1(ANODE2) D39.2(ANODE1) D40.1(ANODE2) D40.2(ANODE1) D41.1(ANODE2) D41.2(ANODE1) D42.1(ANODE2) D42.2(ANODE1) L15.1
N28956999: D35.4(CATHODE1) RN6.16(B)
N28957279: D35.3(CATHODE2) RN6.15(B)
N28957286: D36.4(CATHODE1) RN6.14(B)
N28957291: D36.3(CATHODE2) RN6.13(B)
N28957296: D37.4(CATHODE1) RN6.12(B)
N28957304: D37.3(CATHODE2) RN6.11(B)
N28958157: D38.4(CATHODE1) RN6.10(B)
N28958172: D38.3(CATHODE2) RN6.9(B)
N28958816: D39.4(CATHODE1) RN7.16(B)
N28958825: D39.3(CATHODE2) RN7.15(B)
N28958831: D40.4(CATHODE1) RN7.14(B)
N28958836: D40.3(CATHODE2) RN7.13(B)
N28958844: D41.4(CATHODE1) RN7.12(B)
N28958860: D41.3(CATHODE2) RN7.11(B)
N28958863: D42.4(CATHODE1) RN7.10(B)
N28960141: D42.3(CATHODE2) RN7.9(B)
N29028813: R182.2 U3.13(MDC)
N29028833: R183.2 U3.8(RXD0/MODE0)
N29028836: R184.2 U3.7(RXD1/MODE1)
N29028839: R185.2 U3.11(CRS_DV/MODE2)
N29028854: R186.2 U3.17(TXD0)
N29028859: R187.2 U3.18(TXD1)
N29028863: R188.2 U3.16(TXEN)
N29028931: R180.2 U3.5(XTAL1/CLKIN)
N29041995: R193.1 U1.A6(SSP0_SCK/GPIO2_10)
N29042001: R194.1 U1.A4(SSP0_CMD/GPIO2_8)
N29042019: R195.1 U1.B6(SSP0_DATA0/GPIO2_0)
N29042022: R196.1 U1.C6(SSP0_DATA1/GPIO2_1)
N29042025: R197.1 U1.D6(SSP0_DATA2/GPIO2_2)
N29042028: R198.1 U1.A5(SSP0_DATA3/GPIO2_3)
N29116997: R100.2 R101.2 RN6.6(A)
N29117101: R102.2 R106.2 RN6.8(A)
N29117415: R107.2 R110.2 RN6.4(A)
N29155506: R152.1 SW6.2
N29241645: R206.2 R207.2 RN6.2(A)
N29246306: Q16.3(DRAIN) R211.2
N29246425: D3.3(CATHODE2) R211.1
N29256208: D3.4(CATHODE1) R46.2
N29272408: R11.1 T1.12(YLED-)
N29272682: R10.1 T1.9(GLED+)
N29297998: Q17.3(DRAIN) Q18.3(DRAIN)
N29298001: Q19.3(DRAIN) Q20.3(DRAIN)

Not connected (* = marked no-connect by the designer): FL1 3(IN(OUT)1)* 5(IN(OUT)3)* 6(IN(OUT)4)* 7(OUT(IN)1)* 9(OUT(IN)3)* 10(OUT(IN)4)*; J8 4(P4)*; J13 3* 9* 10* 14* 15* 16* 20* 21* 22* 26* 27* 28* 32* 34* 35* 37* 40* 44* 46* 50* 51* 52* 53* 55* 56* 57* 58* 59* 61* 63* 81* 85* 87* 89* 91* 107* 118* 120*; SW5 3(NC1)* 4(NC2)*; SW6 3(NC1)* 4(NC2)*; SW8 3(NC1)* 4(NC2)*; U1 A2(SSP3_SCK/AUART4_TX/ENET1_1588_EVENT0_OUT/GPIO2_24)* B1(SSP1_SCK/SSP2_D1/ENET0_1588_EVENT2_OUT/GPIO2_12)* B2(SSP3_MISO/SSP3_D0/AUART4_RTS/ENET1_1588_EVENT1_OUT/GPIO2_26)* C1(SSP1_CMD/SSP2_D2/ENET0_1588_EVENT2_IN/GPIO2_13)* C2(SSP3_MOSI/SSP3_CMD/AUART4_RX/ENET1_1588_EVENT0_IN/GPIO2_25)* D1(SSP1_DATA0/SSP2_D6/ENET0_1588_EVENT3_OUT/GPIO2_14)* D2(SSP3_SS0/SSP3_D3/AUART4_CTS/ENET1_1588_EVENT1_IN/GPIO2_27)* E1(SSP1_DATA3/SSP2_D7/ENET0_1588_EVENT3_IN/GPIO2_15)* E3(ENET0_TX_CLK/HSADC_TRIGGER/ENET0_1588_EVENT2_OUT/GPIO4_5)* F3(ENET0_RX_CLK/ENET0_RX_ER/ENET0_1588_EVENT2_IN/GPIO4_13)* F5(AUART2_TX/SSP3_D2/SSP3_D5/GPIO3_9)* F6(AUART2_RX/SSP3_D1/SSP3_D4/GPIO3_8)* G1(ENET0_TXD2/ENET1_TXD0/ENET0_1588_EVENT1_OUT/GPIO4_11)* G2(ENET0_TXD3/ENET1_TXD1/ENET0_1588_EVENT1_IN/GPIO4_12)* H6(AUART2_CTS/I2C1_SCL/SAIF1_BITCLK/GPIO3_10)* H7(AUART2_RTS/I2C1_SDA/SAIF1_LRCLK/GPIO3_11)* J1(ENET0_RXD2/ENET1_RXD0/ENET0_1588_EVENT0_OUT/GPIO4_9)* J2(ENET0_RXD3/ENET1_RXD1/ENET0_1588_EVENT0_IN/GPIO4_10)* J3(ENET0_CRS/ENET1_RX_EN/ENET0_1588_EVENT3_IN/GPIO4_15)* J4(ENET0_COL/ENET1_TX_EN/ENET0_1588_EVENT3_OUT/GPIO4_14)* J5(AUART1_RTS/USB0_ID/TIMROT_ROTARYB/GPIO3_7)* K5(AUART1_CTS/USB0_OVERCURRENT/TIMROT_ROTARYA/GPIO3_6)* K6(AUART3_RTS/CAN1_RX/ENET0_1588_EVENT1_IN/GPIO3_15)* L1(LCD_VSYNC/SAIF1_SDATA0/GPIO1_28)* L5(AUART3_TX/CAN0_RX/ENET0_1588_EVENT0_IN/GPIO3_13)* L6(AUART3_CTS/CAN1_TX/ENET0_1588_EVENT1_OUT/GPIO3_14)* L8(GPMI_RDY3/CAN0_RX/HSADC_TRIGGER/GPIO0_23)* M1(LCD_HSYNC/SAIF1_SDATA1/ETM_TCTL/GPIO1_29)* M5(AUART3_RX/CAN0_TX/ENET0_1588_EVENT0_OUT/GPIO3_12)* M7(~{GPMI_CE2}/CAN1_TX/ENET0_RX_ER/GPIO0_18)* M8(GPMI_RDY2/CAN0_TX/ENET0_TX_ER/GPIO0_22)* M9(~{GPMI_CE3}/CAN1_RX/SAIF1_MCLK/GPIO0_19)* N1(LCD_DOTCLK/SAIF1_MCLK_/ETM_TCLK/GPIO1_30)* N5(LCD_ENABLE/GPIO1_31)* N9(~{GPMI_CE1}/SSP3_D3/GPIO0_17)* P9(~{EMI_CE1})* T17(EMI_ODT1)*; U2 A2(NC1)* E2(NC2)* R7(NC/A15)*; U3 4(XTAL2)*; U5 1(NC)* 2(NC)* 3(NC)* 4(NC)* 5(NC)* 6(NC)* 10(NC)* 11(NC)* 14(NC)* 15(NC)* 20(NC)* 21(NC)* 22(NC)* 23(NC)* 24(NC)* 25(NC)* 26(NC)* 27(NC)* 28(NC)* 33(NC)* 34(NC)* 35(NC)* 38(NC)* 39(NC)* 40(NC)* 45(NC)* 46(NC)* 47(NC)* 48(NC)*; U34 4(NC4)* 6(NC6)* 8(RS485_TXEN)* 9(RTS)* 12(NC12)* 18(NC18)* 24(NC24)*

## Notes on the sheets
sheet 1
- Table of Contents
- 2
- Notes
- 3
- Block Diagram
- 4
- Power tree
- 5
- CPU EIM & DRAM
- 6
- Ethernet, Debug UART
- 7
- i.MX LCD & Boot modes
- 8
- i.MX NAND & SSP
- 9
- i.MX Power supplies
- 10
- i.MX DC/DC converter & JTAG
- 11
- ISM
- 12
- ZigBee
- 13
- Audio - SGTL5000
- 14
- Bluetooth - Wifi mini PCIe
- 15
- USB Hub
- 16
- NFC & IO expander
- 17
- Discrete power supply
sheet 2
- 1. Unless Otherwise Specified:
- All resistors are in ohms, 5%, 1/8 Watt
- All capacitors are in uF, 20%, 50V
- All voltages are DC
- All polarized capacitors are aluminum electrolytic
- 2. Interrupted lines coded with the same letter or letter
      combinations are electrically connected.
- 3. Device type number is for reference only. The number
      varies with the manufacturer.
- Revision table
- 03/07/2011 - Revision 0. Import HEM schematics
- 4. Special signal usage:
- _B Denotes - Active-Low Signal
- <> or [] Denotes - Vectored Signals
- 28/09/2011 - Revision 1. Schematic freeze for first board release
- 5. Interpret diagram in accordance with American
  National Standards Institute specifications, current
  revision, with the exception of logic block symbology.
- 14/12/2011 - Revision 2.
- 02/20/2012 - Add isolation between MX and USB2SER.
- 04/11/2012 - Update component part number to match with manufacturer stock
sheet 5
- Short to match trace length
  to CLK+DATA signals
sheet 6
- ToBT
  interface
- To ZigBee
  interface
- Not present
  on MX283
- On chip regulator
- Not present
  on MX283
- ID floating to indicate B-type
- Isolate Rx/Tx pins to permit
  debug USB hotplug. Otherwise
  Tx pin supplies USB2SER, or
  USB2SER drives DUART RX pin
  low.
sheet 7
- Not present
  on MX283
- corresponds to
  I2C_INT on PDK
  connector
- Not present
  on MX283
- LCD_ENABLE
- LCD port, provisioned for external WVGA
- Power on LED
sheet 8
- Not present
  on MX283
- Not present
  on MX283
- WIFI : SSP0
- Not present
  on MX283
- Not present
  on MX283
sheet 9
- 0.1µF per pin, combine in a single 0.22µF cap for pins side by side
- 0.1µF per pin, combine in a single 0.22µF cap for pins side by side
- 0.1µF per pin, combine in a single 0.22µF cap for pins side by side
